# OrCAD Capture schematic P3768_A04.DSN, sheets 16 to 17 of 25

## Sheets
16 0009_PRE-REG 5V: size Custom
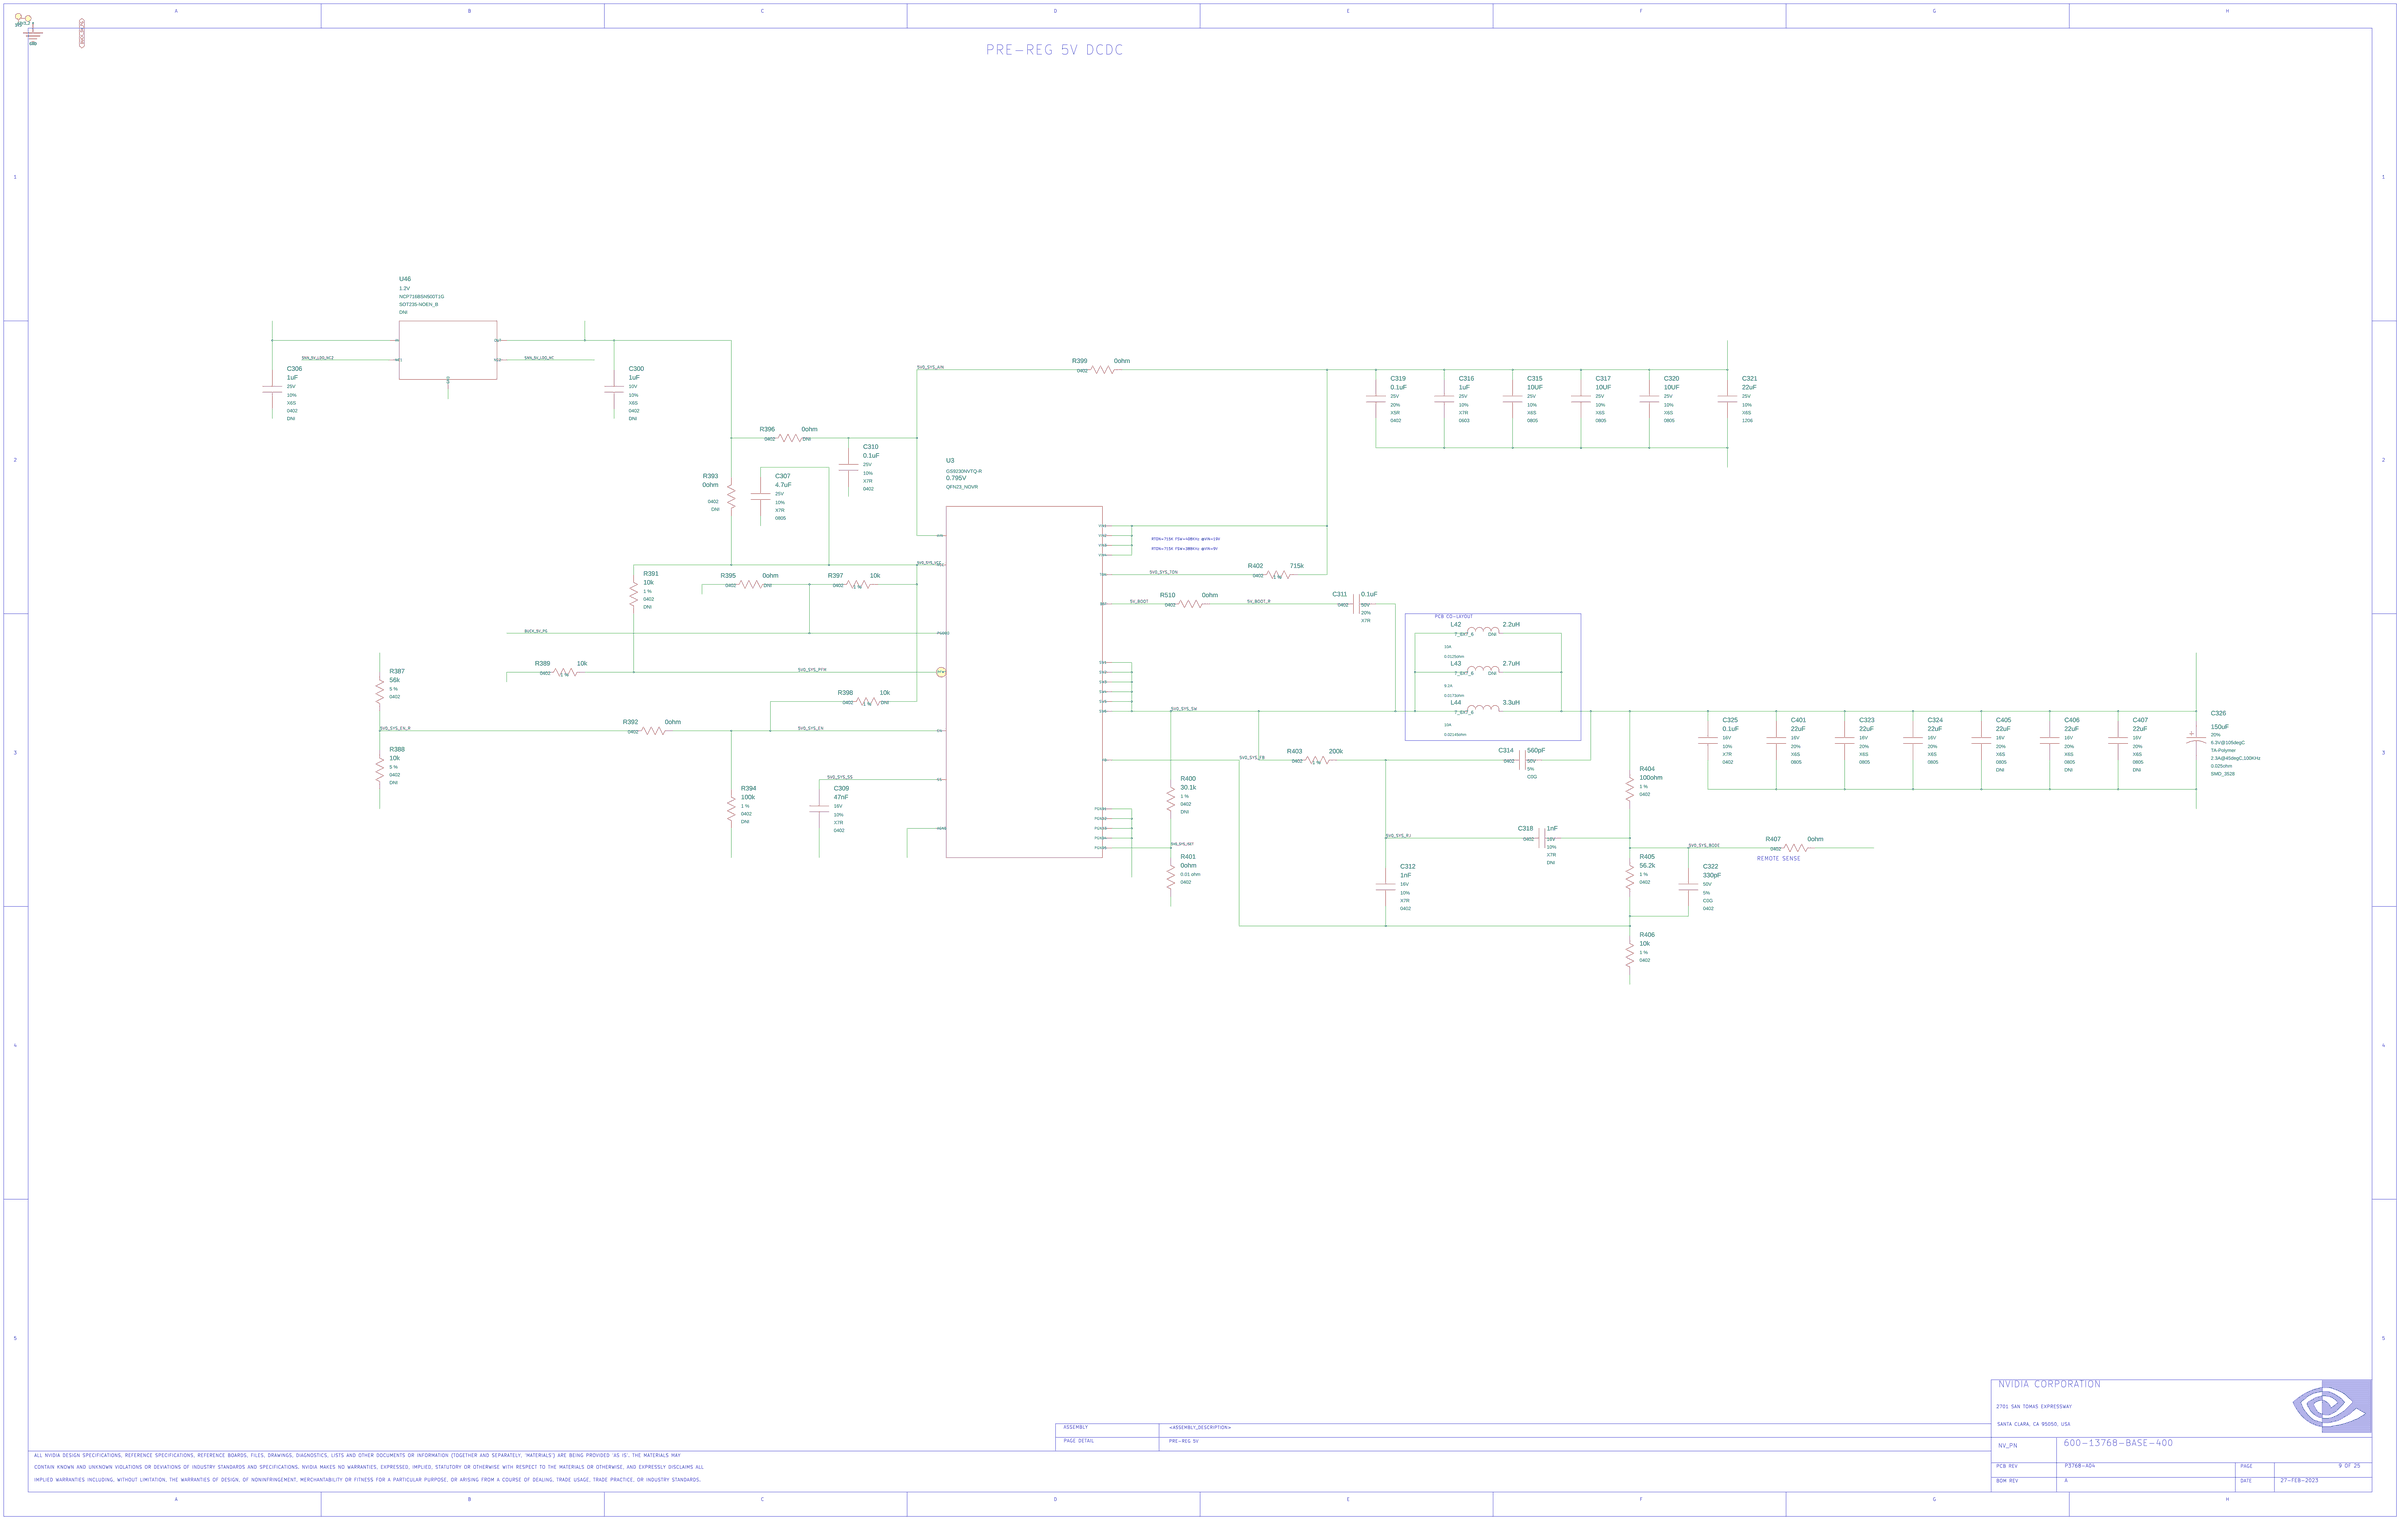
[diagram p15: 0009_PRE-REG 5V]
17 0008_CVM POWER MUX: size Custom
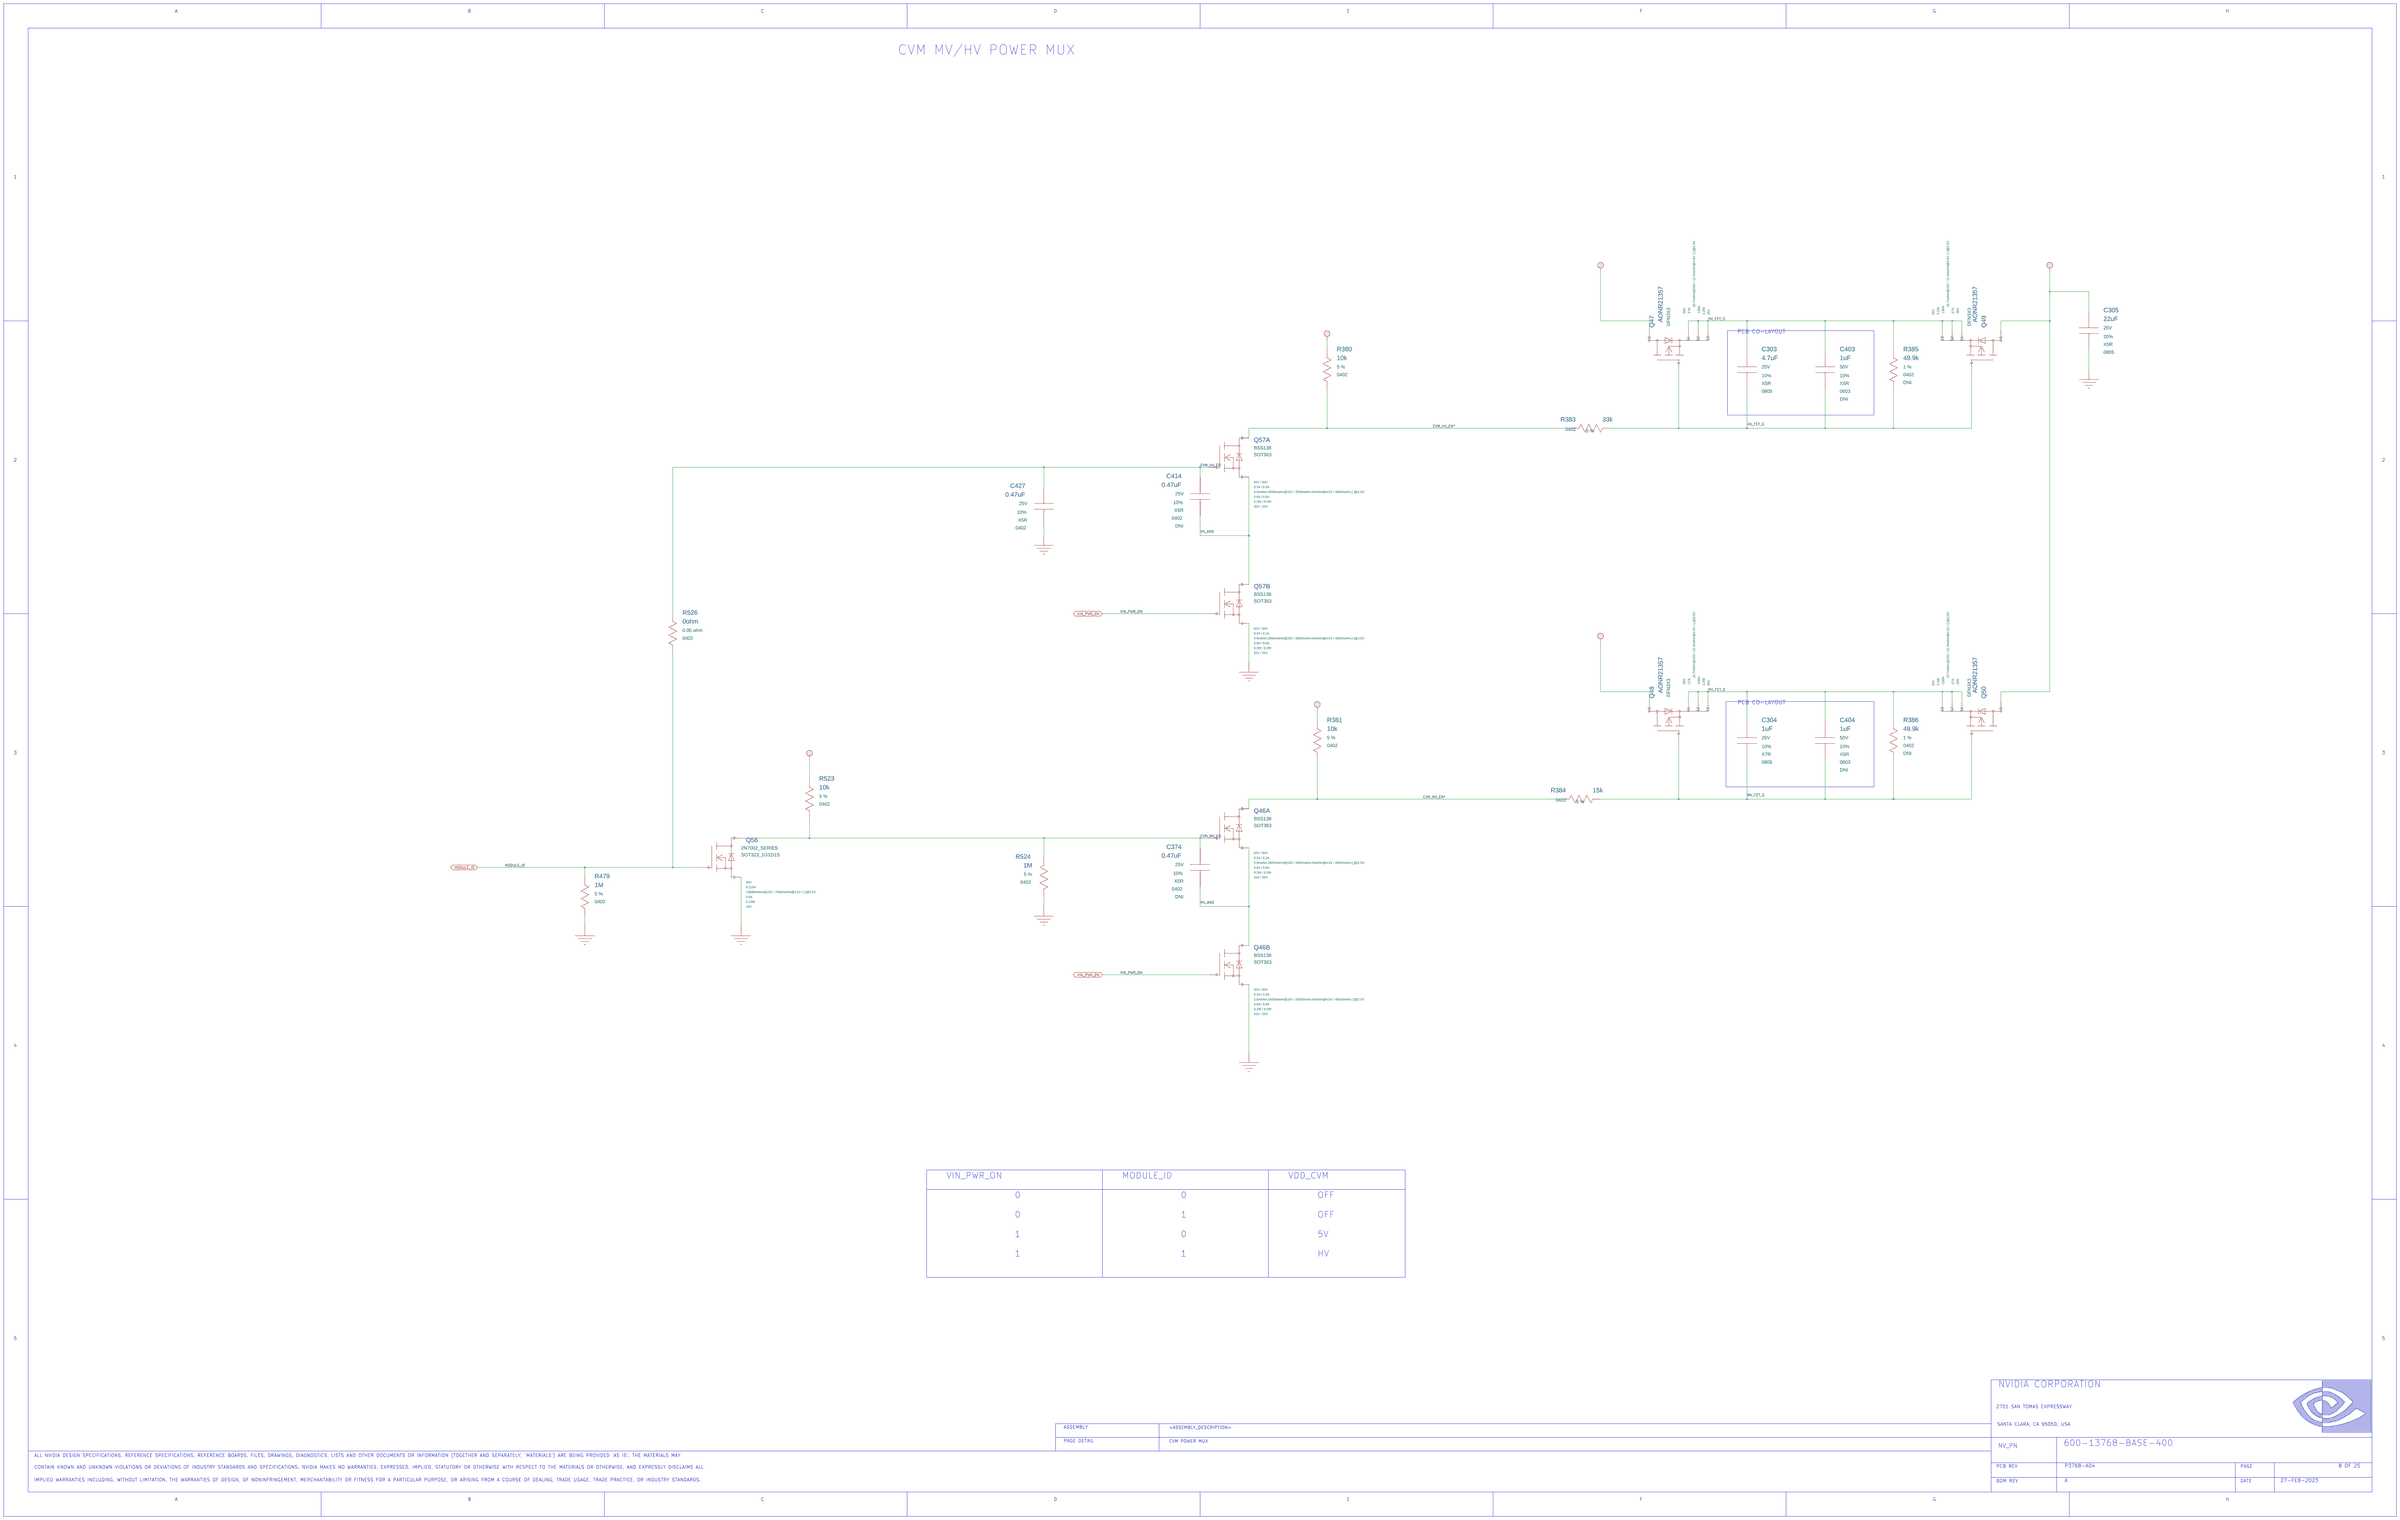
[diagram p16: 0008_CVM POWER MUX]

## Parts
sheet 0008_CVM POWER MUX
C303  4.7uF  [0805U]
C304  1uF  [0805U]
C305  22uF  [0805U]
C374  0.47uF  [0402]
C403  1uF  [0603]
C404  1uF  [0603]
C414  0.47uF  [0402]
C427  0.47uF  [0402]
Q46  Q_FET_N_ENH  [SC70_6]  (sections A,B)
Q47  Q_FET_P_ENH  [DFET_SMD_032X033]
Q48  Q_FET_P_ENH  [DFET_SMD_032X033]
Q49  Q_FET_P_ENH  [DFET_SMD_032X033]
Q50  Q_FET_P_ENH  [DFET_SMD_032X033]
Q56  Q_FET_N_ENH  [SOT323]
Q57  Q_FET_N_ENH  [SC70_6]  (sections A,B)
R380  10k  [0402]
R381  10k  [0402]
R383  33k  [0402]
R384  15k  [0402]
R385  49.9k  [0402]
R386  49.9k  [0402]
R479  1M  [0402]
R523  10k  [0402]
R524  1M  [0402]
R526  0ohm  [0402]
sheet 0009_PRE-REG 5V
C300  1uF  [0402]
C306  1uF  [0402]
C307  4.7uF  [0805U]
C309  47nF  [0402]
C310  0.1uF  [0402]
C311  0.1uF  [0402]
C312  1nF  [0402]
C314  560pF  [0402]
C315  10UF  [0805U]
C316  1uF  [0603]
C317  10UF  [0805U]
C318  1nF  [0402]
C319  0.1uF  [0402]
C320  10UF  [0805U]
C321  22uF  [1206U]
C322  330pF  [0402]
C323  22uF  [0805U]
C324  22uF  [0805U]
C325  0.1uF  [0402]
C326  150uF  [CAP_SMD_3528]
C401  22uF  [0805U]
C405  22uF  [0805U]
C406  22uF  [0805U]
C407  22uF  [0805U]
L42  2.2uH  [IND_NONRKO_SMD_069X069]
L43  2.7uH  [IND_NONRKO_SMD_075X075_B]
L44  3.3uH  [IND_NONRKO_SMD_075X075_B]
R387  56k  [0402]
R388  10k  [0402]
R389  10k  [0402]
R391  10k  [0402]
R392  0ohm  [0402]
R393  0ohm  [0402]
R394  100k  [0402]
R395  0ohm  [0402]
R396  0ohm  [0402]
R397  10k  [0402]
R398  10k  [0402]
R399  0ohm  [0402]
R400  30.1k  [0402]
R401  0ohm  [0402]
R402  715k  [0402]
R403  200k  [0402]
R404  100ohm  [0402]
R405  56.2k  [0402]
R406  10k  [0402]
R407  0ohm  [0402]
R510  0ohm  [0402]
U3  0.795V  [QFN023Q_P050_0040_T028X011_T028X014]
U46  1.2V  [SOT25_5]

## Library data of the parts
C303 = C#1: ASSEMBLY: CVM_POWER_MUX; CDS_LIB: discrete; CDS_PART_NAME: C_0805-4.7UF,X5R,10%,25V,032-2129-000; CDS_PHYS_PART_NAME: C_0805-4.7UF,X5R,10%,25V,032-2129-000-032-2129-000,4.7UF; CDS_SEC: 1; CHIPS_PART_NAME: C; DEVICE_TYPENAME: C_0805-47UFX5R1025V032-2129-000-032-2129-00047UF; DRAWING: @P3768_A04_LIB.P3768_A04(SCH_1):PAGE8; MAT: X5R; MAX_VOLTAGE: 25V; NV_PN: 032-2129-000; PACK_TYPE: 0805; PATH: I95; PHYS_PAGE: 8; ROT: 0; SEC: 1; SIGNAL_MODEL: nv_cap; TOL: 10%; VER: 1; XY: (-3200,5750)
C304 = C#1: ASSEMBLY: CVM_POWER_MUX; CDS_LIB: discrete; CDS_PART_NAME: C_0805-1UF,X7R,10%,25V,036-0117-000; CDS_PHYS_PART_NAME: C_0805-1UF,X7R,10%,25V,036-0117-000-036-0117-000,1UF; CDS_SEC: 1; CHIPS_PART_NAME: C; DEVICE_TYPENAME: C_0805-1UFX7R1025V036-0117-000-036-0117-0001UF; DRAWING: @P3768_A04_LIB.P3768_A04(SCH_1):PAGE8; MAT: X7R; MAX_VOLTAGE: 25V; NV_PN: 036-0117-000; PACK_TYPE: 0805; PATH: I91; PHYS_PAGE: 8; ROT: 0; SEC: 1; SIGNAL_MODEL: nv_cap; TOL: 10%; VER: 1; XY: (-3200,3850)
C305 = C#1: ASSEMBLY: CVM_POWER_MUX; CDS_LIB: discrete; CDS_PART_NAME: C_0805-22UF,X5R,20%,25V,032-1308-000; CDS_PHYS_PART_NAME: C_0805-22UF,X5R,20%,25V,032-1308-000-032-1308-000,22UF; CDS_SEC: 1; CHIPS_PART_NAME: C; DEVICE_TYPENAME: C_0805-22UFX5R2025V032-1308-000-032-1308-00022UF; DRAWING: @P3768_A04_LIB.P3768_A04(SCH_1):PAGE8; MAT: X5R; MAX_VOLTAGE: 25V; NV_PN: 032-1308-000; PACK_TYPE: 0805; PATH: I78; PHYS_PAGE: 8; ROT: 0; SEC: 1; SIGNAL_MODEL: nv_cap; TOL: 20%; VER: 1; XY: (-1450,5950)
C374 = C#1: ASSEMBLY: CVM_POWER_MUX; CDS_LIB: discrete; CDS_PART_NAME: C_0402-0.47UF,X5R,10%,25V,032-0306-000; CDS_PHYS_PART_NAME: C_0402-0.47UF,X5R,10%,25V,032-0306-000-0.47UF,032-0306-000; CDS_SEC: 1; CHIPS_PART_NAME: C; DEVICE_TYPENAME: C_0402-047UFX5R1025V032-0306-000-047UF032-0306-000; DRAWING: @P3768_A04_LIB.P3768_A04(SCH_1):PAGE8; MAT: X5R; MAX_VOLTAGE: 25V; NV_PN: 032-0306-000; PATH: I82; PHYS_PAGE: 8; ROT: 2; SEC: 1; SIGNAL_MODEL: nv_cap; SKU: DNI; TOL: 10%; VER: 1; XY: (-6000,3200)
C403 = C#1: ASSEMBLY: CVM_POWER_MUX; CDS_LIB: discrete; CDS_PART_NAME: C_0603-1UF,X5R,10%,50V,039-0222-000; CDS_PHYS_PART_NAME: C_0603-1UF,X5R,10%,50V,039-0222-000-039-0222-000,1UF; CDS_SEC: 1; CHIPS_PART_NAME: C; DEVICE_TYPENAME: C_0603-1UFX5R1050V039-0222-000-039-0222-0001UF; DRAWING: @P3768_A04_LIB.P3768_A04(SCH_1):PAGE8; MAT: X5R; MAX_VOLTAGE: 50V; NV_PN: 039-0222-000; PATH: I92; PHYS_PAGE: 8; ROT: 0; SEC: 1; SIGNAL_MODEL: nv_cap; SKU: DNI; TOL: 10%; VER: 1; XY: (-2800,5750)
C404 = C#1: ASSEMBLY: CVM_POWER_MUX; CDS_LIB: discrete; CDS_PART_NAME: C_0603-1UF,X5R,10%,50V,039-0222-000; CDS_PHYS_PART_NAME: C_0603-1UF,X5R,10%,50V,039-0222-000-039-0222-000,1UF; CDS_SEC: 1; CHIPS_PART_NAME: C; DEVICE_TYPENAME: C_0603-1UFX5R1050V039-0222-000-039-0222-0001UF; DRAWING: @P3768_A04_LIB.P3768_A04(SCH_1):PAGE8; MAT: X5R; MAX_VOLTAGE: 50V; NV_PN: 039-0222-000; PATH: I93; PHYS_PAGE: 8; ROT: 0; SEC: 1; SIGNAL_MODEL: nv_cap; SKU: DNI; TOL: 10%; VER: 1; XY: (-2800,3850)
C414 = C#1: ASSEMBLY: CVM_POWER_MUX; CDS_LIB: discrete; CDS_PART_NAME: C_0402-0.47UF,X5R,10%,25V,032-0306-000; CDS_PHYS_PART_NAME: C_0402-0.47UF,X5R,10%,25V,032-0306-000-0.47UF,032-0306-000; CDS_SEC: 1; CHIPS_PART_NAME: C; DEVICE_TYPENAME: C_0402-047UFX5R1025V032-0306-000-047UF032-0306-000; DRAWING: @P3768_A04_LIB.P3768_A04(SCH_1):PAGE8; MAT: X5R; MAX_VOLTAGE: 25V; NV_PN: 032-0306-000; PATH: I177; PHYS_PAGE: 8; ROT: 2; SEC: 1; SIGNAL_MODEL: nv_cap; SKU: DNI; TOL: 10%; VER: 1; XY: (-6000,5100)
C427 = C#1: ASSEMBLY: CVM_POWER_MUX; CDS_LIB: discrete; CDS_PART_NAME: C_0402-0.47UF,X5R,10%,25V,032-0306-000; CDS_PHYS_PART_NAME: C_0402-0.47UF,X5R,10%,25V,032-0306-000-0.47UF,032-0306-000; CDS_SEC: 1; CHIPS_PART_NAME: C; DEVICE_TYPENAME: C_0402-047UFX5R1025V032-0306-000-047UF032-0306-000; DRAWING: @P3768_A04_LIB.P3768_A04(SCH_1):PAGE8; MAT: X5R; MAX_VOLTAGE: 25V; NV_PN: 032-0306-000; PATH: I178; PHYS_PAGE: 8; ROT: 2; SEC: 1; SIGNAL_MODEL: nv_cap; TOL: 10%; VER: 1; XY: (-6800,5050)
Q46 = Q_FET_N_ENH: ASSEMBLY: CVM_POWER_MUX; CDS_LIB: discrete; CDS_PART_NAME: Q_FET_N_ENH_SOT363-BSS138,50V / 50V,3.5MOHM,3500MOHM@10V / 2500MOHM,0MOHM@4.5V / 4500MOHM,[ ]@2.5V,0.2A / 0.2A,0.6A / 0.6A,20V / 20V,0.2W / 0.2W,[ ],[ ]@10V / 1NC,1NC@4.5V / [ ],[ ]@2.5V,300-1278-000; CDS_PHYS_PART_NAME: Q_FET_N_ENH_SOT363-BSS138,50V / 50V,3.5MOHM,3500MOHM@10V / 2500MOHM,0MOHM@4.5V / 4500MOHM,[ ]@2.5V,0.2A / 0.2A,0.6A / 0.6A,20VB; CDS_SEC: 2; CONTINUOUS_CURRENT: 0.2A / 0.2A; DEVICE_TYPENAME: Q_FET_N_ENH_SOT363-BSS13850V50V35MOHM3500MOHM10V2500MOHM0MOHM45V4500MOHM25V02A02A06A06A20VB; DRAWING: @P3768_A04_LIB.P3768_A04(SCH_1):PAGE8; MAX_CURRENT: 0.6A / 0.6A; MAX_VOLTAGE: 50V / 50V; MAX_WATTAGE: 0.2W / 0.2W; NV_NAME: BSS138; NV_PN: 300-1278-000; PACK_TYPE: SOT363; PATH: I170; PHYS_PAGE: 8; Q_G: [ ],[ ]@10V / 1nC,1nC@4.5V / [ ],[ ]@2.5V; ROT: 0; R_DS_ON: 3.5mohm,3500mohm@10V / 2500mohm,0mohm@4.5V / 4500mohm,[ ]@2.5V; SEC: 2; SEC_TYPE: SOT363; VER: 2; V_BE_GS: 20V / 20V; XY: (-5850,2700)
Q47 = Q_FET_P_ENH: ASSEMBLY: CVM_POWER_MUX; CDS_LIB: discrete; CDS_PART_NAME: Q_FET_P_ENH_DFN3X3-AONR21357,-30V,10.7MOHM@10V / 12.3MOHM@4.5V / [ ]@2.5V,-17A,-136A,25V,3.2W,70NC@10V / 35NC@4.5V / [ ]@2.5V,300-1070-000; CDS_PHYS_PART_NAME: Q_FET_P_ENH_DFN3X3-AONR21357,-30V,10.7MOHM@10V / 12.3MOHM@4.5V / [ ]@2.5V,-17A,-136A,25V,3.2W,70NC@10V / 35NC@4.5V / [ ]@2.5V,B; CDS_SEC: 1; CONTINUOUS_CURRENT: -17A; DEVICE_TYPENAME: Q_FET_P_ENH_DFN3X3-AONR21357-30V107MOHM10V123MOHM45V25V-17A-136A25V32W70NC10V35NC45V25VB; DRAWING: @P3768_A04_LIB.P3768_A04(SCH_1):PAGE8; MAX_CURRENT: -136A; MAX_VOLTAGE: -30V; MAX_WATTAGE: 3.2W; NV_NAME: AONR21357; NV_PN: 300-1070-000; PACK_TYPE: DFN3X3; PATH: I72; PHYS_PAGE: 8; Q_G: 70nC@10V / 35nC@4.5V / [ ]@2.5V; ROT: 1; R_DS_ON: 10.7mohm@10V / 12.3mohm@4.5V / [ ]@2.5V; SEC: 1; VER: 8; V_BE_GS: 25V; XY: (-3600,5850)
Q48 = Q_FET_P_ENH: ASSEMBLY: CVM_POWER_MUX; CDS_LIB: discrete; CDS_PART_NAME: Q_FET_P_ENH_DFN3X3-AONR21357,-30V,10.7MOHM@10V / 12.3MOHM@4.5V / [ ]@2.5V,-17A,-136A,25V,3.2W,70NC@10V / 35NC@4.5V / [ ]@2.5V,300-1070-000; CDS_PHYS_PART_NAME: Q_FET_P_ENH_DFN3X3-AONR21357,-30V,10.7MOHM@10V / 12.3MOHM@4.5V / [ ]@2.5V,-17A,-136A,25V,3.2W,70NC@10V / 35NC@4.5V / [ ]@2.5V,B; CDS_SEC: 1; CONTINUOUS_CURRENT: -17A; DEVICE_TYPENAME: Q_FET_P_ENH_DFN3X3-AONR21357-30V107MOHM10V123MOHM45V25V-17A-136A25V32W70NC10V35NC45V25VB; DRAWING: @P3768_A04_LIB.P3768_A04(SCH_1):PAGE8; MAX_CURRENT: -136A; MAX_VOLTAGE: -30V; MAX_WATTAGE: 3.2W; NV_NAME: AONR21357; NV_PN: 300-1070-000; PACK_TYPE: DFN3X3; PATH: I69; PHYS_PAGE: 8; Q_G: 70nC@10V / 35nC@4.5V / [ ]@2.5V; ROT: 1; R_DS_ON: 10.7mohm@10V / 12.3mohm@4.5V / [ ]@2.5V; SEC: 1; VER: 8; V_BE_GS: 25V; XY: (-3600,3950)
Q49 = Q_FET_P_ENH: ASSEMBLY: CVM_POWER_MUX; CDS_LIB: discrete; CDS_PART_NAME: Q_FET_P_ENH_DFN3X3-AONR21357,-30V,10.7MOHM@10V / 12.3MOHM@4.5V / [ ]@2.5V,-17A,-136A,25V,3.2W,70NC@10V / 35NC@4.5V / [ ]@2.5V,300-1070-000; CDS_PHYS_PART_NAME: Q_FET_P_ENH_DFN3X3-AONR21357,-30V,10.7MOHM@10V / 12.3MOHM@4.5V / [ ]@2.5V,-17A,-136A,25V,3.2W,70NC@10V / 35NC@4.5V / [ ]@2.5V,B; CDS_SEC: 1; CONTINUOUS_CURRENT: -17A; DEVICE_TYPENAME: Q_FET_P_ENH_DFN3X3-AONR21357-30V107MOHM10V123MOHM45V25V-17A-136A25V32W70NC10V35NC45V25VB; DRAWING: @P3768_A04_LIB.P3768_A04(SCH_1):PAGE8; MAX_CURRENT: -136A; MAX_VOLTAGE: -30V; MAX_WATTAGE: 3.2W; NV_NAME: AONR21357; NV_PN: 300-1070-000; PACK_TYPE: DFN3X3; PATH: I76; PHYS_PAGE: 8; Q_G: 70nC@10V / 35nC@4.5V / [ ]@2.5V; ROT: 7; R_DS_ON: 10.7mohm@10V / 12.3mohm@4.5V / [ ]@2.5V; SEC: 1; VER: 8; V_BE_GS: 25V; XY: (-2000,5850)
Q50 = Q_FET_P_ENH: ASSEMBLY: CVM_POWER_MUX; CDS_LIB: discrete; CDS_PART_NAME: Q_FET_P_ENH_DFN3X3-AONR21357,-30V,10.7MOHM@10V / 12.3MOHM@4.5V / [ ]@2.5V,-17A,-136A,25V,3.2W,70NC@10V / 35NC@4.5V / [ ]@2.5V,300-1070-000; CDS_PHYS_PART_NAME: Q_FET_P_ENH_DFN3X3-AONR21357,-30V,10.7MOHM@10V / 12.3MOHM@4.5V / [ ]@2.5V,-17A,-136A,25V,3.2W,70NC@10V / 35NC@4.5V / [ ]@2.5V,B; CDS_SEC: 1; CONTINUOUS_CURRENT: -17A; DEVICE_TYPENAME: Q_FET_P_ENH_DFN3X3-AONR21357-30V107MOHM10V123MOHM45V25V-17A-136A25V32W70NC10V35NC45V25VB; DRAWING: @P3768_A04_LIB.P3768_A04(SCH_1):PAGE8; MAX_CURRENT: -136A; MAX_VOLTAGE: -30V; MAX_WATTAGE: 3.2W; NV_NAME: AONR21357; NV_PN: 300-1070-000; PACK_TYPE: DFN3X3; PATH: I75; PHYS_PAGE: 8; Q_G: 70nC@10V / 35nC@4.5V / [ ]@2.5V; ROT: 7; R_DS_ON: 10.7mohm@10V / 12.3mohm@4.5V / [ ]@2.5V; SEC: 1; VER: 8; V_BE_GS: 25V; XY: (-2000,3950)
Q56 = Q_FET_N_ENH#1: ASSEMBLY: CVM_POWER_MUX; CDS_LIB: discrete; CDS_PART_NAME: Q_FET_N_ENH_SOT323_1G1D1S-2N7002_SERIES,60V,13500MOHM@10V / 7500MOHM@4.5V / [ ]@2.5V,0.115A,0.8A,20V,0.15W,[ ]@10V / 0.5NC@4.5V / [ ]@2.5V,300-1133-000; CDS_PHYS_PART_NAME: Q_FET_N_ENH_SOT323_1G1D1S-2N7002_SERIES,60V,13500MOHM@10V / 7500MOHM@4.5V / [ ]@2.5V,0.115A,0.8A,20V,0.15W,[ ]@10V / 0.5NC@4.5B; CDS_SEC: 1; CONTINUOUS_CURRENT: 0.115A; CaptureCellPackProp: Q_FET_N_ENH##1; DEVICE_TYPENAME: Q_FET_N_ENH_SOT323_1G1D1S-2N7002_SERIES60V13500MOHM10V7500MOHM45V25V0115A08A20V015W10V05NC45B; DRAWING: @P3768_A04_LIB.P3768_A04(SCH_1):PAGE8; MAX_CURRENT: 0.8A; MAX_VOLTAGE: 60V; MAX_WATTAGE: 0.15W; NV_NAME: 2N7002_SERIES; NV_PN: 300-1133-000; PACK_TYPE: SOT323_1G1D1S; PATH: I166; PHYS_PAGE: 8; Q_G: [ ]@10V / 0.5nC@4.5V / [ ]@2.5V; ROT: 0; R_DS_ON: 13500mohm@10V / 7500mohm@4.5V / [ ]@2.5V; SEC: 1; VER: 2; V_BE_GS: 20V; XY: (-8450,3250)
Q57 = Q_FET_N_ENH: ASSEMBLY: CVM_POWER_MUX; CDS_LIB: discrete; CDS_PART_NAME: Q_FET_N_ENH_SOT363-BSS138,50V / 50V,3.5MOHM,3500MOHM@10V / 2500MOHM,0MOHM@4.5V / 4500MOHM,[ ]@2.5V,0.2A / 0.2A,0.6A / 0.6A,20V / 20V,0.2W / 0.2W,[ ],[ ]@10V / 1NC,1NC@4.5V / [ ],[ ]@2.5V,300-1278-000; CDS_PHYS_PART_NAME: Q_FET_N_ENH_SOT363-BSS138,50V / 50V,3.5MOHM,3500MOHM@10V / 2500MOHM,0MOHM@4.5V / 4500MOHM,[ ]@2.5V,0.2A / 0.2A,0.6A / 0.6A,20VB; CDS_SEC: 1; CONTINUOUS_CURRENT: 0.2A / 0.2A; DEVICE_TYPENAME: Q_FET_N_ENH_SOT363-BSS13850V50V35MOHM3500MOHM10V2500MOHM0MOHM45V4500MOHM25V02A02A06A06A20VB; DRAWING: @P3768_A04_LIB.P3768_A04(SCH_1):PAGE8; MAX_CURRENT: 0.6A / 0.6A; MAX_VOLTAGE: 50V / 50V; MAX_WATTAGE: 0.2W / 0.2W; NV_NAME: BSS138; NV_PN: 300-1278-000; PACK_TYPE: SOT363; PATH: I169; PHYS_PAGE: 8; Q_G: [ ],[ ]@10V / 1nC,1nC@4.5V / [ ],[ ]@2.5V; ROT: 0; R_DS_ON: 3.5mohm,3500mohm@10V / 2500mohm,0mohm@4.5V / 4500mohm,[ ]@2.5V; SEC: 1; SEC_TYPE: SOT363; VER: 2; V_BE_GS: 20V / 20V; XY: (-5850,5300)
R380 = R: ASSEMBLY: CVM_POWER_MUX; CDS_LIB: discrete; CDS_PART_NAME: R_0402-10K,5 %,62.5MW,195-0486-000; CDS_PHYS_PART_NAME: R_0402-10K,5 %,62.5MW,195-0486-000-10K,195-0486-000; CDS_SEC: 1; DEVICE_TYPENAME: R_0402-10K5625MW195-0486-000-10K195-0486-000; DRAWING: @P3768_A04_LIB.P3768_A04(SCH_1):PAGE8; MAX_WATTAGE: 62.5mW; NV_PN: 195-0486-000; PATH: I80; PHYS_PAGE: 8; ROT: 0; SEC: 1; SIGNAL_MODEL: nv_res; TOL: 5 %; VER: 2; XY: (-5350,5750)
R381 = R: ASSEMBLY: CVM_POWER_MUX; CDS_LIB: discrete; CDS_PART_NAME: R_0402-10K,5 %,62.5MW,195-0486-000; CDS_PHYS_PART_NAME: R_0402-10K,5 %,62.5MW,195-0486-000-10K,195-0486-000; CDS_SEC: 1; DEVICE_TYPENAME: R_0402-10K5625MW195-0486-000-10K195-0486-000; DRAWING: @P3768_A04_LIB.P3768_A04(SCH_1):PAGE8; MAX_WATTAGE: 62.5mW; NV_PN: 195-0486-000; PATH: I81; PHYS_PAGE: 8; ROT: 0; SEC: 1; SIGNAL_MODEL: nv_res; TOL: 5 %; VER: 2; XY: (-5400,3850)
R383 = R#1: ASSEMBLY: CVM_POWER_MUX; CDS_LIB: discrete; CDS_PART_NAME: R_0402-33K,5 %,62.5MW,195-0571-000; CDS_PHYS_PART_NAME: R_0402-33K,5 %,62.5MW,195-0571-000-195-0571-000,33K; CDS_SEC: 1; CHIPS_PART_NAME: R; DEVICE_TYPENAME: R_0402-33K5625MW195-0571-000-195-0571-00033K; DRAWING: @P3768_A04_LIB.P3768_A04(SCH_1):PAGE8; MAX_WATTAGE: 62.5mW; NV_PN: 195-0571-000; PATH: I94; PHYS_PAGE: 8; ROT: 0; SEC: 1; SIGNAL_MODEL: nv_res; TOL: 5 %; VER: 1; XY: (-4000,5450)
R384 = R#1: ASSEMBLY: CVM_POWER_MUX; CDS_LIB: discrete; CDS_PART_NAME: R_0402-15K,5 %,62.5MW,195-0515-000; CDS_PHYS_PART_NAME: R_0402-15K,5 %,62.5MW,195-0515-000-15K,195-0515-000; CDS_SEC: 1; CHIPS_PART_NAME: R; DEVICE_TYPENAME: R_0402-15K5625MW195-0515-000-15K195-0515-000; DRAWING: @P3768_A04_LIB.P3768_A04(SCH_1):PAGE8; MAX_WATTAGE: 62.5mW; NV_PN: 195-0515-000; PATH: I136; PHYS_PAGE: 8; ROT: 0; SEC: 1; SIGNAL_MODEL: nv_res; TOL: 5 %; VER: 1; XY: (-4050,3550)
R385 = R: ASSEMBLY: CVM_POWER_MUX; CDS_LIB: discrete; CDS_PART_NAME: R_0402-49.9K,1 %,62.5MW,195-0340-000; CDS_PHYS_PART_NAME: R_0402-49.9K,1 %,62.5MW,195-0340-000-195-0340-000,49.9K; CDS_SEC: 1; DEVICE_TYPENAME: R_0402-499K1625MW195-0340-000-195-0340-000499K; DRAWING: @P3768_A04_LIB.P3768_A04(SCH_1):PAGE8; MAX_WATTAGE: 62.5mW; NV_PN: 195-0340-000; PATH: I87; PHYS_PAGE: 8; ROT: 0; SEC: 1; SIGNAL_MODEL: nv_res; SKU: DNI; TOL: 1 %; VER: 2; XY: (-2450,5750)
R386 = R: ASSEMBLY: CVM_POWER_MUX; CDS_LIB: discrete; CDS_PART_NAME: R_0402-49.9K,1 %,62.5MW,195-0340-000; CDS_PHYS_PART_NAME: R_0402-49.9K,1 %,62.5MW,195-0340-000-195-0340-000,49.9K; CDS_SEC: 1; DEVICE_TYPENAME: R_0402-499K1625MW195-0340-000-195-0340-000499K; DRAWING: @P3768_A04_LIB.P3768_A04(SCH_1):PAGE8; MAX_WATTAGE: 62.5mW; NV_PN: 195-0340-000; PATH: I89; PHYS_PAGE: 8; ROT: 0; SEC: 1; SIGNAL_MODEL: nv_res; SKU: DNI; TOL: 1 %; VER: 2; XY: (-2450,3850)
R479 = R: ASSEMBLY: CVM_POWER_MUX; CDS_LIB: discrete; CDS_PART_NAME: R_0402-1M,5 %,62.5MW,195-0488-000; CDS_PHYS_PART_NAME: R_0402-1M,5 %,62.5MW,195-0488-000-195-0488-000,1M; CDS_SEC: 1; DEVICE_TYPENAME: R_0402-1M5625MW195-0488-000-195-0488-0001M; DRAWING: @P3768_A04_LIB.P3768_A04(SCH_1):PAGE8; MAX_WATTAGE: 62.5mW; NV_PN: 195-0488-000; PATH: I151; PHYS_PAGE: 8; ROT: 0; SEC: 1; SIGNAL_MODEL: nv_res; TOL: 5 %; VER: 2; XY: (-9150,3050)
R523 = R: ASSEMBLY: CVM_POWER_MUX; CDS_LIB: discrete; CDS_PART_NAME: R_0402-10K,5 %,62.5MW,195-0486-000; CDS_PHYS_PART_NAME: R_0402-10K,5 %,62.5MW,195-0486-000-10K,195-0486-000; CDS_SEC: 1; DEVICE_TYPENAME: R_0402-10K5625MW195-0486-000-10K195-0486-000; DRAWING: @P3768_A04_LIB.P3768_A04(SCH_1):PAGE8; MAX_WATTAGE: 62.5mW; NV_PN: 195-0486-000; PATH: I114; PHYS_PAGE: 8; ROT: 0; SEC: 1; SIGNAL_MODEL: nv_res; TOL: 5 %; VER: 2; XY: (-8000,3550)
R524 = R: ASSEMBLY: CVM_POWER_MUX; CDS_LIB: discrete; CDS_PART_NAME: R_0402-1M,5 %,62.5MW,195-0488-000; CDS_PHYS_PART_NAME: R_0402-1M,5 %,62.5MW,195-0488-000-195-0488-000,1M; CDS_SEC: 1; DEVICE_TYPENAME: R_0402-1M5625MW195-0488-000-195-0488-0001M; DRAWING: @P3768_A04_LIB.P3768_A04(SCH_1):PAGE8; MAX_WATTAGE: 62.5mW; NV_PN: 195-0488-000; PATH: I99; PHYS_PAGE: 8; ROT: 2; SEC: 1; SIGNAL_MODEL: nv_res; TOL: 5 %; VER: 2; XY: (-6800,3150)
R526 = R: ASSEMBLY: CVM_POWER_MUX; CDS_LIB: discrete; CDS_PART_NAME: R_0402-0OHM,0.05 OHM,62.5MW,195-2655-000; CDS_PHYS_PART_NAME: R_0402-0OHM,0.05 OHM,62.5MW,195-2655-000-0OHM,195-2655-000; CDS_SEC: 1; DEVICE_TYPENAME: R_0402-0OHM005OHM625MW195-2655-000-0OHM195-2655-000; DRAWING: @P3768_A04_LIB.P3768_A04(SCH_1):PAGE8; MAX_WATTAGE: 62.5mW; NV_PN: 195-2655-000; PATH: I165; PHYS_PAGE: 8; ROT: 0; SEC: 1; SIGNAL_MODEL: nv_res; TOL: 0.05 ohm; VER: 2; XY: (-8700,4400)
C300 = C#1: ASSEMBLY: PS_5V; CDS_LIB: discrete; CDS_PART_NAME: C_0402-1UF,X6S,10%,10V,032-0776-000; CDS_PHYS_PART_NAME: C_0402-1UF,X6S,10%,10V,032-0776-000-032-0776-000,1UF; CDS_SEC: 1; CHIPS_PART_NAME: C; DEVICE_TYPENAME: C_0402-1UFX6S1010V032-0776-000-032-0776-0001UF; DRAWING: @P3768_A04_LIB.P3768_A04(SCH_1):PAGE9; MAT: X6S; MAX_VOLTAGE: 10V; NV_PN: 032-0776-000; PATH: I129; PHYS_PAGE: 9; PSPICETEMPLATE: X^@REFDES  %1    %2   @NV_PN; ROT: 0; SEC: 1; SIGNAL_MODEL: nv_cap; SKU: DNI; TOL: 10%; VER: 1; XY: (-9000,5650)
C306 = C#1: ASSEMBLY: PS_5V; CDS_LIB: discrete; CDS_PART_NAME: C_0402-1UF,X6S,10%,25V,032-0782-000; CDS_PHYS_PART_NAME: C_0402-1UF,X6S,10%,25V,032-0782-000-032-0782-000,1UF; CDS_SEC: 1; CHIPS_PART_NAME: C; DEVICE_TYPENAME: C_0402-1UFX6S1025V032-0782-000-032-0782-0001UF; DRAWING: @P3768_A04_LIB.P3768_A04(SCH_1):PAGE9; MAT: X6S; MAX_VOLTAGE: 25V; NV_PN: 032-0782-000; PATH: I128; PHYS_PAGE: 9; PSPICETEMPLATE: X^@REFDES  %1    %2   @NV_PN; ROT: 0; SEC: 1; SIGNAL_MODEL: nv_cap; SKU: DNI; TOL: 10%; VER: 1; XY: (-10750,5650)
C307 = C#1: ASSEMBLY: PS_5V; CDS_LIB: discrete; CDS_PART_NAME: C_0805-4.7UF,X7R,10%,25V,032-0207-000; CDS_PHYS_PART_NAME: C_0805-4.7UF,X7R,10%,25V,032-0207-000-032-0207-000,4.7UF; CDS_SEC: 1; CHIPS_PART_NAME: C; DEVICE_TYPENAME: C_0805-47UFX7R1025V032-0207-000-032-0207-00047UF; DRAWING: @P3768_A04_LIB.P3768_A04(SCH_1):PAGE9; MAT: X7R; MAX_VOLTAGE: 25V; NV_PN: 032-0207-000; PACK_TYPE: 0805; PATH: I134; PHYS_PAGE: 9; PSPICETEMPLATE: X^@REFDES  %1    %2   @NV_PN; ROT: 0; SEC: 1; SIGNAL_MODEL: nv_cap; TOL: 10%; VER: 1; XY: (-8250,5100)
C309 = C#1: ASSEMBLY: PS_5V; CDS_LIB: discrete; CDS_PART_NAME: C_0402-47NF,X7R,10%,16V,036-0018-000; CDS_PHYS_PART_NAME: C_0402-47NF,X7R,10%,16V,036-0018-000-036-0018-000,47NF; CDS_SEC: 1; CHIPS_PART_NAME: C; DEVICE_TYPENAME: C_0402-47NFX7R1016V036-0018-000-036-0018-00047NF; DRAWING: @P3768_A04_LIB.P3768_A04(SCH_1):PAGE9; MAT: X7R; MAX_VOLTAGE: 16V; NV_PN: 036-0018-000; PATH: I165; PHYS_PAGE: 9; PSPICETEMPLATE: X^@REFDES  %1    %2   @NV_PN; ROT: 0; SEC: 1; SIGNAL_MODEL: nv_cap; TOL: 10%; VER: 1; XY: (-7950,3500)
C310 = C#1: ASSEMBLY: PS_5V; CDS_LIB: discrete; CDS_PART_NAME: C_0402-0.1UF,X7R,10%,25V,032-1700-000; CDS_PHYS_PART_NAME: C_0402-0.1UF,X7R,10%,25V,032-1700-000-0.1UF,032-1700-000; CDS_SEC: 1; CHIPS_PART_NAME: C; DEVICE_TYPENAME: C_0402-01UFX7R1025V032-1700-000-01UF032-1700-000; DRAWING: @P3768_A04_LIB.P3768_A04(SCH_1):PAGE9; MAT: X7R; MAX_VOLTAGE: 25V; NV_PN: 032-1700-000; PATH: I135; PHYS_PAGE: 9; PSPICETEMPLATE: X^@REFDES  %1    %2   @NV_PN; ROT: 0; SEC: 1; SIGNAL_MODEL: nv_cap; TOL: 10%; VER: 1; XY: (-7800,5250)
C311 = C: ASSEMBLY: PS_5V; CDS_LIB: discrete; CDS_PART_NAME: C_0402-0.1UF,X7R,20%,50V,032-0892-000; CDS_PHYS_PART_NAME: C_0402-0.1UF,X7R,20%,50V,032-0892-000-0.1UF,032-0892-000; CDS_SEC: 1; DEVICE_TYPENAME: C_0402-01UFX7R2050V032-0892-000-01UF032-0892-000; DRAWING: @P3768_A04_LIB.P3768_A04(SCH_1):PAGE9; MAT: X7R; MAX_VOLTAGE: 50V; NV_PN: 032-0892-000; PATH: I145; PHYS_PAGE: 9; PSPICETEMPLATE: X^@REFDES  %1    %2   @NV_PN; ROT: 0; SEC: 1; SIGNAL_MODEL: nv_cap; TOL: 20%; VER: 2; XY: (-5200,4550)
C312 = C#1: ASSEMBLY: PS_5V; CDS_LIB: discrete; CDS_PART_NAME: C_0402-1NF,X7R,10%,16V,036-0012-000; CDS_PHYS_PART_NAME: C_0402-1NF,X7R,10%,16V,036-0012-000-036-0012-000,1NF; CDS_SEC: 1; CHIPS_PART_NAME: C; DEVICE_TYPENAME: C_0402-1NFX7R1016V036-0012-000-036-0012-0001NF; DRAWING: @P3768_A04_LIB.P3768_A04(SCH_1):PAGE9; MAT: X7R; MAX_VOLTAGE: 16V; NV_PN: 036-0012-000; PATH: I160; PHYS_PAGE: 9; PSPICETEMPLATE: X^@REFDES  %1    %2   @NV_PN; ROT: 0; SEC: 1; SIGNAL_MODEL: nv_cap; TOL: 10%; VER: 1; XY: (-5050,3100)
C314 = C: ASSEMBLY: PS_5V; CDS_LIB: discrete; CDS_PART_NAME: C_0402-560PF,C0G,5%,50V,035-0295-000; CDS_PHYS_PART_NAME: C_0402-560PF,C0G,5%,50V,035-0295-000-035-0295-000,560PF; CDS_SEC: 1; DEVICE_TYPENAME: C_0402-560PFC0G550V035-0295-000-035-0295-000560PF; DRAWING: @P3768_A04_LIB.P3768_A04(SCH_1):PAGE9; MAT: C0G; MAX_VOLTAGE: 50V; NV_PN: 035-0295-000; PATH: I196; PHYS_PAGE: 9; ROT: 0; SEC: 1; SIGNAL_MODEL: nv_cap; TOL: 5%; VER: 2; XY: (-4350,3750)
C315 = C#1: ASSEMBLY: PS_5V; CDS_LIB: discrete; CDS_PART_NAME: C_0805-10UF,X6S,10%,25V,032-0728-000; CDS_PHYS_PART_NAME: C_0805-10UF,X6S,10%,25V,032-0728-000-032-0728-000,10UF; CDS_SEC: 1; CHIPS_PART_NAME: C; DEVICE_TYPENAME: C_0805-10UFX6S1025V032-0728-000-032-0728-00010UF; DRAWING: @P3768_A04_LIB.P3768_A04(SCH_1):PAGE9; MAT: X6S; MAX_VOLTAGE: 25V; NV_PN: 032-0728-000; PACK_TYPE: 0805; PATH: I143; PHYS_PAGE: 9; PSPICETEMPLATE: X^@REFDES  %1    %2   @NV_PN; ROT: 0; SEC: 1; SIGNAL_MODEL: nv_cap; TOL: 10%; VER: 1; XY: (-4400,5600)
C316 = C#1: ASSEMBLY: PS_5V; CDS_LIB: discrete; CDS_PART_NAME: C_0603-1UF,X7R,10%,25V,032-0253-000; CDS_PHYS_PART_NAME: C_0603-1UF,X7R,10%,25V,032-0253-000-032-0253-000,1UF; CDS_SEC: 1; CHIPS_PART_NAME: C; DEVICE_TYPENAME: C_0603-1UFX7R1025V032-0253-000-032-0253-0001UF; DRAWING: @P3768_A04_LIB.P3768_A04(SCH_1):PAGE9; MAT: X7R; MAX_VOLTAGE: 25V; NV_PN: 032-0253-000; PATH: I190; PHYS_PAGE: 9; PSPICETEMPLATE: X^@REFDES  %1    %2   @NV_PN; ROT: 0; SEC: 1; SIGNAL_MODEL: nv_cap; TOL: 10%; VER: 1; XY: (-4750,5600)
C317 = C#1: ASSEMBLY: PS_5V; CDS_LIB: discrete; CDS_PART_NAME: C_0805-10UF,X6S,10%,25V,032-0728-000; CDS_PHYS_PART_NAME: C_0805-10UF,X6S,10%,25V,032-0728-000-032-0728-000,10UF; CDS_SEC: 1; CHIPS_PART_NAME: C; DEVICE_TYPENAME: C_0805-10UFX6S1025V032-0728-000-032-0728-00010UF; DRAWING: @P3768_A04_LIB.P3768_A04(SCH_1):PAGE9; MAT: X6S; MAX_VOLTAGE: 25V; NV_PN: 032-0728-000; PACK_TYPE: 0805; PATH: I142; PHYS_PAGE: 9; PSPICETEMPLATE: X^@REFDES  %1    %2   @NV_PN; ROT: 0; SEC: 1; SIGNAL_MODEL: nv_cap; TOL: 10%; VER: 1; XY: (-4050,5600)
C318 = C: ASSEMBLY: PS_5V; CDS_LIB: discrete; CDS_PART_NAME: C_0402-1NF,X7R,10%,16V,036-0012-000; CDS_PHYS_PART_NAME: C_0402-1NF,X7R,10%,16V,036-0012-000-036-0012-000,1NF; CDS_SEC: 1; DEVICE_TYPENAME: C_0402-1NFX7R1016V036-0012-000-036-0012-0001NF; DRAWING: @P3768_A04_LIB.P3768_A04(SCH_1):PAGE9; MAT: X7R; MAX_VOLTAGE: 16V; NV_PN: 036-0012-000; PATH: I158; PHYS_PAGE: 9; PSPICETEMPLATE: X^@REFDES  %1    %2   @NV_PN; ROT: 0; SEC: 1; SIGNAL_MODEL: nv_cap; SKU: DNI; TOL: 10%; VER: 2; XY: (-4250,3350)
C319 = C#1: ASSEMBLY: PS_5V; CDS_LIB: discrete; CDS_PART_NAME: C_0402-0.1UF,X5R,20%,25V,039-0208-000; CDS_PHYS_PART_NAME: C_0402-0.1UF,X5R,20%,25V,039-0208-000-0.1UF,039-0208-000; CDS_SEC: 1; CHIPS_PART_NAME: C; DEVICE_TYPENAME: C_0402-01UFX5R2025V039-0208-000-01UF039-0208-000; DRAWING: @P3768_A04_LIB.P3768_A04(SCH_1):PAGE9; MAT: X5R; MAX_VOLTAGE: 25V; NV_PN: 039-0208-000; PATH: I193; PHYS_PAGE: 9; ROT: 0; SEC: 1; SIGNAL_MODEL: nv_cap; TOL: 20%; VER: 1; XY: (-5100,5600)
C320 = C#1: ASSEMBLY: PS_5V; CDS_LIB: discrete; CDS_PART_NAME: C_0805-10UF,X6S,10%,25V,032-0728-000; CDS_PHYS_PART_NAME: C_0805-10UF,X6S,10%,25V,032-0728-000-032-0728-000,10UF; CDS_SEC: 1; CHIPS_PART_NAME: C; DEVICE_TYPENAME: C_0805-10UFX6S1025V032-0728-000-032-0728-00010UF; DRAWING: @P3768_A04_LIB.P3768_A04(SCH_1):PAGE9; MAT: X6S; MAX_VOLTAGE: 25V; NV_PN: 032-0728-000; PACK_TYPE: 0805; PATH: I141; PHYS_PAGE: 9; PSPICETEMPLATE: X^@REFDES  %1    %2   @NV_PN; ROT: 0; SEC: 1; SIGNAL_MODEL: nv_cap; TOL: 10%; VER: 1; XY: (-3700,5600)
C321 = C#1: ASSEMBLY: PS_5V; CDS_LIB: discrete; CDS_PART_NAME: C_1206-22UF,X6S,10%,25V,032-1215-000; CDS_PHYS_PART_NAME: C_1206-22UF,X6S,10%,25V,032-1215-000-032-1215-000,22UF; CDS_SEC: 1; CHIPS_PART_NAME: C; DEVICE_TYPENAME: C_1206-22UFX6S1025V032-1215-000-032-1215-00022UF; DRAWING: @P3768_A04_LIB.P3768_A04(SCH_1):PAGE9; MAT: X6S; MAX_VOLTAGE: 25V; NV_PN: 032-1215-000; PACK_TYPE: 1206; PATH: I192; PHYS_PAGE: 9; ROT: 0; SEC: 1; SIGNAL_MODEL: nv_cap; TOL: 10%; VER: 1; XY: (-3300,5600)
C322 = C#1: ASSEMBLY: PS_5V; CDS_LIB: discrete; CDS_PART_NAME: C_0402-330PF,C0G,5%,50V,035-0066-000; CDS_PHYS_PART_NAME: C_0402-330PF,C0G,5%,50V,035-0066-000-035-0066-000,330PF; CDS_SEC: 1; CHIPS_PART_NAME: C; DEVICE_TYPENAME: C_0402-330PFC0G550V035-0066-000-035-0066-000330PF; DRAWING: @P3768_A04_LIB.P3768_A04(SCH_1):PAGE9; MAT: C0G; MAX_VOLTAGE: 50V; NV_PN: 035-0066-000; PATH: I156; PHYS_PAGE: 9; PSPICETEMPLATE: X^@REFDES  %1    %2   @NV_PN; ROT: 0; SEC: 1; SIGNAL_MODEL: nv_cap; TOL: 5%; VER: 1; XY: (-3500,3100)
C323 = C#1: ASSEMBLY: PS_5V; CDS_LIB: discrete; CDS_PART_NAME: C_0805-22UF,X6S,20%,16V,032-0559-000; CDS_PHYS_PART_NAME: C_0805-22UF,X6S,20%,16V,032-0559-000-032-0559-000,22UF; CDS_SEC: 1; CHIPS_PART_NAME: C; DEVICE_TYPENAME: C_0805-22UFX6S2016V032-0559-000-032-0559-00022UF; DRAWING: @P3768_A04_LIB.P3768_A04(SCH_1):PAGE9; MAT: X6S; MAX_VOLTAGE: 16V; NV_PN: 032-0559-000; PACK_TYPE: 0805; PATH: I149; PHYS_PAGE: 9; PSPICETEMPLATE: X^@REFDES  %1    %2   @NV_PN; ROT: 0; SEC: 1; SIGNAL_MODEL: nv_cap; TOL: 20%; VER: 1; XY: (-2700,3850)
C324 = C#1: ASSEMBLY: PS_5V; CDS_LIB: discrete; CDS_PART_NAME: C_0805-22UF,X6S,20%,16V,032-0559-000; CDS_PHYS_PART_NAME: C_0805-22UF,X6S,20%,16V,032-0559-000-032-0559-000,22UF; CDS_SEC: 1; CHIPS_PART_NAME: C; DEVICE_TYPENAME: C_0805-22UFX6S2016V032-0559-000-032-0559-00022UF; DRAWING: @P3768_A04_LIB.P3768_A04(SCH_1):PAGE9; MAT: X6S; MAX_VOLTAGE: 16V; NV_PN: 032-0559-000; PACK_TYPE: 0805; PATH: I150; PHYS_PAGE: 9; PSPICETEMPLATE: X^@REFDES  %1    %2   @NV_PN; ROT: 0; SEC: 1; SIGNAL_MODEL: nv_cap; TOL: 20%; VER: 1; XY: (-2350,3850)
C325 = C#1: ASSEMBLY: PS_5V; CDS_LIB: discrete; CDS_PART_NAME: C_0402-0.1UF,X7R,10%,16V,032-0793-000; CDS_PHYS_PART_NAME: C_0402-0.1UF,X7R,10%,16V,032-0793-000-0.1UF,032-0793-000; CDS_SEC: 1; CHIPS_PART_NAME: C; DEVICE_TYPENAME: C_0402-01UFX7R1016V032-0793-000-01UF032-0793-000; DRAWING: @P3768_A04_LIB.P3768_A04(SCH_1):PAGE9; MAT: X7R; MAX_VOLTAGE: 16V; NV_PN: 032-0793-000; PATH: I151; PHYS_PAGE: 9; PSPICETEMPLATE: X^@REFDES  %1    %2   @NV_PN; ROT: 0; SEC: 1; SIGNAL_MODEL: nv_cap; TOL: 10%; VER: 1; XY: (-3400,3850)
C326 = C_POL: ASSEMBLY: PS_5V; CDS_LIB: discrete; CDS_PART_NAME: C_POL_SMD_3528-150UF,TA-POLYMER,20%,6.3V@105DEGC,0.025OHM,9.999UH,2.3A@45DEGC,100KHZ,032-0681-000; CDS_PHYS_PART_NAME: C_POL_SMD_3528-150UF,TA-POLYMER,20%,6.3V@105DEGC,0.025OHM,9.999UH,2.3A@45DEGC,100KHZ,032-0681-000-032-0681-000,150UF; CDS_SEC: 1; DEVICE_TYPENAME: C_POL_SMD_3528-150UFTA-POLYMER2063V105DEGC0025OHM9999UH23A45DEGC100KHZ032-0681-000-032-0681-000150UF; DRAWING: @P3768_A04_LIB.P3768_A04(SCH_1):PAGE9; ESL: 9.999uH; ESR: 0.025ohm; MAT: TA-Polymer; MAX_VOLTAGE: 6.3V@105degC; NV_PN: 032-0681-000; PACK_TYPE: SMD_3528; PATH: I184; PHYS_PAGE: 9; RIPPLE_CURRENT: 2.3A@45degC,100KHz; ROT: 0; SEC: 1; SIGNAL_MODEL: nv_capp; TOL: 20%; VER: 1; XY: (-900,3850)
C401 = C#1: ASSEMBLY: PS_3V3; CDS_LIB: discrete; CDS_PART_NAME: C_0805-22UF,X6S,20%,16V,032-0559-000; CDS_PHYS_PART_NAME: C_0805-22UF,X6S,20%,16V,032-0559-000-032-0559-000,22UF; CDS_SEC: 1; CHIPS_PART_NAME: C; DEVICE_TYPENAME: C_0805-22UFX6S2016V032-0559-000-032-0559-00022UF; DRAWING: @P3768_A04_LIB.P3768_A04(SCH_1):PAGE9; MAT: X6S; MAX_VOLTAGE: 16V; NV_PN: 032-0559-000; PACK_TYPE: 0805; PATH: I185; PHYS_PAGE: 9; PSPICETEMPLATE: X^@REFDES  %1    %2   @NV_PN; ROT: 0; SEC: 1; SIGNAL_MODEL: nv_cap; TOL: 20%; VER: 1; XY: (-3050,3850)
C405 = C#1: ASSEMBLY: PS_5V; CDS_LIB: discrete; CDS_PART_NAME: C_0805-22UF,X6S,20%,16V,032-0559-000; CDS_PHYS_PART_NAME: C_0805-22UF,X6S,20%,16V,032-0559-000-032-0559-000,22UF; CDS_SEC: 1; CHIPS_PART_NAME: C; DEVICE_TYPENAME: C_0805-22UFX6S2016V032-0559-000-032-0559-00022UF; DRAWING: @P3768_A04_LIB.P3768_A04(SCH_1):PAGE9; MAT: X6S; MAX_VOLTAGE: 16V; NV_PN: 032-0559-000; PACK_TYPE: 0805; PATH: I200; PHYS_PAGE: 9; PSPICETEMPLATE: X^@REFDES  %1    %2   @NV_PN; ROT: 0; SEC: 1; SIGNAL_MODEL: nv_cap; SKU: DNI; TOL: 20%; VER: 1; XY: (-2000,3850)
C406 = C#1: ASSEMBLY: PS_5V; CDS_LIB: discrete; CDS_PART_NAME: C_0805-22UF,X6S,20%,16V,032-0559-000; CDS_PHYS_PART_NAME: C_0805-22UF,X6S,20%,16V,032-0559-000-032-0559-000,22UF; CDS_SEC: 1; CHIPS_PART_NAME: C; DEVICE_TYPENAME: C_0805-22UFX6S2016V032-0559-000-032-0559-00022UF; DRAWING: @P3768_A04_LIB.P3768_A04(SCH_1):PAGE9; MAT: X6S; MAX_VOLTAGE: 16V; NV_PN: 032-0559-000; PACK_TYPE: 0805; PATH: I201; PHYS_PAGE: 9; PSPICETEMPLATE: X^@REFDES  %1    %2   @NV_PN; ROT: 0; SEC: 1; SIGNAL_MODEL: nv_cap; SKU: DNI; TOL: 20%; VER: 1; XY: (-1650,3850)
C407 = C#1: ASSEMBLY: PS_5V; CDS_LIB: discrete; CDS_PART_NAME: C_0805-22UF,X6S,20%,16V,032-0559-000; CDS_PHYS_PART_NAME: C_0805-22UF,X6S,20%,16V,032-0559-000-032-0559-000,22UF; CDS_SEC: 1; CHIPS_PART_NAME: C; DEVICE_TYPENAME: C_0805-22UFX6S2016V032-0559-000-032-0559-00022UF; DRAWING: @P3768_A04_LIB.P3768_A04(SCH_1):PAGE9; MAT: X6S; MAX_VOLTAGE: 16V; NV_PN: 032-0559-000; PACK_TYPE: 0805; PATH: I202; PHYS_PAGE: 9; PSPICETEMPLATE: X^@REFDES  %1    %2   @NV_PN; ROT: 0; SEC: 1; SIGNAL_MODEL: nv_cap; SKU: DNI; TOL: 20%; VER: 1; XY: (-1300,3850)
L42 = L: ASSEMBLY: PS_5V; CDS_LIB: discrete; CDS_PART_NAME: L_7_6X7_6-2.2UH,ALLOY POWDER,20%,10A,12A,0.0125OHM,50@300KHZ,0HZ,130-1236-000; CDS_PHYS_PART_NAME: L_7_6X7_6-2.2UH,ALLOY POWDER,20%,10A,12A,0.0125OHM,50@300KHZ,0HZ,130-1236-000-130-1236-000,2.2UH; CDS_SEC: 1; CONTINUOUS_CURRENT: 10A; DC_RESISTANCE: 0.0125ohm; DEVICE_TYPENAME: L_7_6X7_6-22UHALLOYPOWDER2010A12A00125OHM50300KHZ0HZ130-1236-000-130-1236-00022UH; DRAWING: @P3768_A04_LIB.P3768_A04(SCH_1):PAGE9; MAT: Alloy Powder; MAX_CURRENT: 12A; NV_PN: 130-1236-000; PACK_TYPE: 7_6X7_6; PATH: I199; PHYS_PAGE: 9; Q: 50@300KHz; ROT: 0; SEC: 1; SELF_RESONANCE_FREQ: 0Hz; SIGNAL_MODEL: nv_ind; SKU: DNI; TOL: 20%; VER: 1; XY: (-4550,4400)
L43 = L: ASSEMBLY: PS_5V; CDS_LIB: discrete; CDS_PART_NAME: L_7_6X7_6-2.7UH,COMPOSITE,20%,9.2A,12.8A,0.0173OHM,[ ]@[ ],32MHZ,130-1439-000; CDS_PHYS_PART_NAME: L_7_6X7_6-2.7UH,COMPOSITE,20%,9.2A,12.8A,0.0173OHM,[ ]@[ ],32MHZ,130-1439-000-130-1439-000,2.7UH; CDS_SEC: 1; CONTINUOUS_CURRENT: 9.2A; DC_RESISTANCE: 0.0173ohm; DEVICE_TYPENAME: L_7_6X7_6-27UHCOMPOSITE2092A128A00173OHM32MHZ130-1439-000-130-1439-00027UH; DRAWING: @P3768_A04_LIB.P3768_A04(SCH_1):PAGE9; MAT: Composite; MAX_CURRENT: 12.8A; NV_PN: 130-1439-000; PACK_TYPE: 7_6X7_6; PATH: I198; PHYS_PAGE: 9; Q: [ ]@[ ]; ROT: 0; SEC: 1; SELF_RESONANCE_FREQ: 32MHz; SIGNAL_MODEL: nv_ind; SKU: DNI; TOL: 20%; VER: 1; XY: (-4550,4200)
L44 = L: ASSEMBLY: PS_5V; CDS_LIB: discrete; CDS_PART_NAME: L_7_6X7_6-3.3UH,COMPOSITE,20%,10A,12.3A,0.02145OHM,[ ]@[ ],29MHZ,130-1404-000; CDS_PHYS_PART_NAME: L_7_6X7_6-3.3UH,COMPOSITE,20%,10A,12.3A,0.02145OHM,[ ]@[ ],29MHZ,130-1404-000-130-1404-000,3.3UH; CDS_SEC: 1; CONTINUOUS_CURRENT: 10A; DC_RESISTANCE: 0.02145ohm; DEVICE_TYPENAME: L_7_6X7_6-33UHCOMPOSITE2010A123A002145OHM29MHZ130-1404-000-130-1404-00033UH; DRAWING: @P3768_A04_LIB.P3768_A04(SCH_1):PAGE9; MAT: Composite; MAX_CURRENT: 12.3A; NV_PN: 130-1404-000; PACK_TYPE: 7_6X7_6; PATH: I197; PHYS_PAGE: 9; Q: [ ]@[ ]; ROT: 0; SEC: 1; SELF_RESONANCE_FREQ: 29MHz; SIGNAL_MODEL: nv_ind; TOL: 20%; VER: 1; XY: (-4550,4000)
R387 = R: ASSEMBLY: PS_5V; CDS_LIB: discrete; CDS_PART_NAME: R_0402-56K,5 %,62.5MW,195-0613-000; CDS_PHYS_PART_NAME: R_0402-56K,5 %,62.5MW,195-0613-000-195-0613-000,56K; CDS_SEC: 1; DEVICE_TYPENAME: R_0402-56K5625MW195-0613-000-195-0613-00056K; DRAWING: @P3768_A04_LIB.P3768_A04(SCH_1):PAGE9; MAX_WATTAGE: 62.5mW; NV_PN: 195-0613-000; PATH: I169; PHYS_PAGE: 9; ROT: 0; SEC: 1; SIGNAL_MODEL: nv_res; TOL: 5 %; VER: 2; XY: (-10200,4100)
R388 = R: ASSEMBLY: PS_5V; CDS_LIB: discrete; CDS_PART_NAME: R_0402-10K,5 %,62.5MW,195-0486-000; CDS_PHYS_PART_NAME: R_0402-10K,5 %,62.5MW,195-0486-000-10K,195-0486-000; CDS_SEC: 1; DEVICE_TYPENAME: R_0402-10K5625MW195-0486-000-10K195-0486-000; DRAWING: @P3768_A04_LIB.P3768_A04(SCH_1):PAGE9; MAX_WATTAGE: 62.5mW; NV_PN: 195-0486-000; PATH: I170; PHYS_PAGE: 9; PSPICETEMPLATE: X^@REFDES  %1    %2   @NV_PN; ROT: 0; SEC: 1; SIGNAL_MODEL: nv_res; SKU: DNI; TOL: 5 %; VER: 2; XY: (-10200,3700)
R389 = R#1: ASSEMBLY: PS_5V; CDS_LIB: discrete; CDS_PART_NAME: R_0402-10K,1 %,62.5MW,195-0004-000; CDS_PHYS_PART_NAME: R_0402-10K,1 %,62.5MW,195-0004-000-10K,195-0004-000; CDS_SEC: 1; CHIPS_PART_NAME: R; DEVICE_TYPENAME: R_0402-10K1625MW195-0004-000-10K195-0004-000; DRAWING: @P3768_A04_LIB.P3768_A04(SCH_1):PAGE9; MAX_WATTAGE: 62.5mW; NV_PN: 195-0004-000; PATH: I168; PHYS_PAGE: 9; PSPICETEMPLATE: X^@REFDES  %1    %2   @NV_PN; ROT: 0; SEC: 1; SIGNAL_MODEL: nv_res; TOL: 1 %; VER: 1; XY: (-9250,4200)
R391 = R: ASSEMBLY: PS_5V; CDS_LIB: discrete; CDS_PART_NAME: R_0402-10K,1 %,62.5MW,195-0004-000; CDS_PHYS_PART_NAME: R_0402-10K,1 %,62.5MW,195-0004-000-10K,195-0004-000; CDS_SEC: 1; DEVICE_TYPENAME: R_0402-10K1625MW195-0004-000-10K195-0004-000; DRAWING: @P3768_A04_LIB.P3768_A04(SCH_1):PAGE9; MAX_WATTAGE: 62.5mW; NV_PN: 195-0004-000; PATH: I171; PHYS_PAGE: 9; PSPICETEMPLATE: X^@REFDES  %1    %2   @NV_PN; ROT: 0; SEC: 1; SIGNAL_MODEL: nv_res; SKU: DNI; TOL: 1 %; VER: 2; XY: (-8900,4600)
R392 = R#1: ASSEMBLY: PS_5V; CDS_LIB: discrete; CDS_PART_NAME: R_0402-0OHM,0.05 OHM,62.5MW,195-2655-000; CDS_PHYS_PART_NAME: R_0402-0OHM,0.05 OHM,62.5MW,195-2655-000-0OHM,195-2655-000; CDS_SEC: 1; CHIPS_PART_NAME: R; DEVICE_TYPENAME: R_0402-0OHM005OHM625MW195-2655-000-0OHM195-2655-000; DRAWING: @P3768_A04_LIB.P3768_A04(SCH_1):PAGE9; MAX_WATTAGE: 62.5mW; NV_PN: 195-2655-000; PATH: I167; PHYS_PAGE: 9; PSPICETEMPLATE: X^@REFDES  %1    %2   @NV_PN; ROT: 0; SEC: 1; SIGNAL_MODEL: nv_res; TOL: 0.05 ohm; VER: 1; XY: (-8800,3900)
R393 = R: ASSEMBLY: PS_5V; CDS_LIB: discrete; CDS_PART_NAME: R_0402-0OHM,0.05 OHM,62.5MW,195-2655-000; CDS_PHYS_PART_NAME: R_0402-0OHM,0.05 OHM,62.5MW,195-2655-000-0OHM,195-2655-000; CDS_SEC: 1; DEVICE_TYPENAME: R_0402-0OHM005OHM625MW195-2655-000-0OHM195-2655-000; DRAWING: @P3768_A04_LIB.P3768_A04(SCH_1):PAGE9; MAX_WATTAGE: 62.5mW; NV_PN: 195-2655-000; PATH: I133; PHYS_PAGE: 9; PSPICETEMPLATE: X^@REFDES  %1    %2   @NV_PN; ROT: 2; SEC: 1; SIGNAL_MODEL: nv_res; SKU: DNI; TOL: 0.05 ohm; VER: 2; XY: (-8400,5100)
R394 = R: ASSEMBLY: PS_5V; CDS_LIB: discrete; CDS_PART_NAME: R_0402-100K,1 %,62.5MW,195-0005-000; CDS_PHYS_PART_NAME: R_0402-100K,1 %,62.5MW,195-0005-000-100K,195-0005-000; CDS_SEC: 1; DEVICE_TYPENAME: R_0402-100K1625MW195-0005-000-100K195-0005-000; DRAWING: @P3768_A04_LIB.P3768_A04(SCH_1):PAGE9; MAX_WATTAGE: 62.5mW; NV_PN: 195-0005-000; PATH: I164; PHYS_PAGE: 9; PSPICETEMPLATE: X^@REFDES  %1    %2   @NV_PN; ROT: 0; SEC: 1; SIGNAL_MODEL: nv_res; SKU: DNI; TOL: 1 %; VER: 2; XY: (-8400,3500)
R395 = R#1: ASSEMBLY: PS_5V; CDS_LIB: discrete; CDS_PART_NAME: R_0402-0OHM,0.05 OHM,62.5MW,195-2655-000; CDS_PHYS_PART_NAME: R_0402-0OHM,0.05 OHM,62.5MW,195-2655-000-0OHM,195-2655-000; CDS_SEC: 1; CHIPS_PART_NAME: R; DEVICE_TYPENAME: R_0402-0OHM005OHM625MW195-2655-000-0OHM195-2655-000; DRAWING: @P3768_A04_LIB.P3768_A04(SCH_1):PAGE9; MAX_WATTAGE: 62.5mW; NV_PN: 195-2655-000; PATH: I194; PHYS_PAGE: 9; ROT: 0; SEC: 1; SIGNAL_MODEL: nv_res; SKU: DNI; TOL: 0.05 ohm; VER: 1; XY: (-8300,4650)
R396 = R#1: ASSEMBLY: PS_5V; CDS_LIB: discrete; CDS_PART_NAME: R_0402-0OHM,0.05 OHM,62.5MW,195-2655-000; CDS_PHYS_PART_NAME: R_0402-0OHM,0.05 OHM,62.5MW,195-2655-000-0OHM,195-2655-000; CDS_SEC: 1; CHIPS_PART_NAME: R; DEVICE_TYPENAME: R_0402-0OHM005OHM625MW195-2655-000-0OHM195-2655-000; DRAWING: @P3768_A04_LIB.P3768_A04(SCH_1):PAGE9; MAX_WATTAGE: 62.5mW; NV_PN: 195-2655-000; PATH: I132; PHYS_PAGE: 9; PSPICETEMPLATE: X^@REFDES  %1    %2   @NV_PN; ROT: 0; SEC: 1; SIGNAL_MODEL: nv_res; SKU: DNI; TOL: 0.05 ohm; VER: 1; XY: (-8100,5400)
R397 = R#1: ASSEMBLY: PS_5V; CDS_LIB: discrete; CDS_PART_NAME: R_0402-10K,1 %,62.5MW,195-0004-000; CDS_PHYS_PART_NAME: R_0402-10K,1 %,62.5MW,195-0004-000-10K,195-0004-000; CDS_SEC: 1; CHIPS_PART_NAME: R; DEVICE_TYPENAME: R_0402-10K1625MW195-0004-000-10K195-0004-000; DRAWING: @P3768_A04_LIB.P3768_A04(SCH_1):PAGE9; MAX_WATTAGE: 62.5mW; NV_PN: 195-0004-000; PATH: I195; PHYS_PAGE: 9; ROT: 0; SEC: 1; SIGNAL_MODEL: nv_res; TOL: 1 %; VER: 1; XY: (-7750,4650)
R398 = R#1: ASSEMBLY: PS_5V; CDS_LIB: discrete; CDS_PART_NAME: R_0402-10K,1 %,62.5MW,195-0004-000; CDS_PHYS_PART_NAME: R_0402-10K,1 %,62.5MW,195-0004-000-10K,195-0004-000; CDS_SEC: 1; CHIPS_PART_NAME: R; DEVICE_TYPENAME: R_0402-10K1625MW195-0004-000-10K195-0004-000; DRAWING: @P3768_A04_LIB.P3768_A04(SCH_1):PAGE9; MAX_WATTAGE: 62.5mW; NV_PN: 195-0004-000; PATH: I166; PHYS_PAGE: 9; PSPICETEMPLATE: X^@REFDES  %1    %2   @NV_PN; ROT: 0; SEC: 1; SIGNAL_MODEL: nv_res; SKU: DNI; TOL: 1 %; VER: 1; XY: (-7700,4050)
R399 = R#1: ASSEMBLY: PS_5V; CDS_LIB: discrete; CDS_PART_NAME: R_0402-0OHM,0.05 OHM,62.5MW,195-2655-000; CDS_PHYS_PART_NAME: R_0402-0OHM,0.05 OHM,62.5MW,195-2655-000-0OHM,195-2655-000; CDS_SEC: 1; CHIPS_PART_NAME: R; DEVICE_TYPENAME: R_0402-0OHM005OHM625MW195-2655-000-0OHM195-2655-000; DRAWING: @P3768_A04_LIB.P3768_A04(SCH_1):PAGE9; MAX_WATTAGE: 62.5mW; NV_PN: 195-2655-000; PATH: I136; PHYS_PAGE: 9; ROT: 0; SEC: 1; SIGNAL_MODEL: nv_res; TOL: 0.05 ohm; VER: 1; XY: (-6500,5750)
R400 = R: ASSEMBLY: PS_5V; CDS_LIB: discrete; CDS_PART_NAME: R_0402-30.1K,1 %,62.5MW,195-0235-000; CDS_PHYS_PART_NAME: R_0402-30.1K,1 %,62.5MW,195-0235-000-195-0235-000,30.1K; CDS_SEC: 1; DEVICE_TYPENAME: R_0402-301K1625MW195-0235-000-195-0235-000301K; DRAWING: @P3768_A04_LIB.P3768_A04(SCH_1):PAGE9; MAX_WATTAGE: 62.5mW; NV_PN: 195-0235-000; PATH: I162; PHYS_PAGE: 9; ROT: 0; SEC: 1; SIGNAL_MODEL: nv_res; SKU: DNI; TOL: 1 %; VER: 2; XY: (-6150,3550)
R401 = R: ASSEMBLY: PS_5V; CDS_LIB: discrete; CDS_PART_NAME: R_0402-0OHM,0.01 OHM,0.125W,195-1691-000; CDS_PHYS_PART_NAME: R_0402-0OHM,0.01 OHM,0.125W,195-1691-000-0OHM,195-1691-000; CDS_SEC: 1; DEVICE_TYPENAME: R_0402-0OHM001OHM0125W195-1691-000-0OHM195-1691-000; DRAWING: @P3768_A04_LIB.P3768_A04(SCH_1):PAGE9; MAX_WATTAGE: 0.125W; NV_PN: 195-1691-000; PATH: I163; PHYS_PAGE: 9; ROT: 0; SEC: 1; SIGNAL_MODEL: nv_res; TOL: 0.01 ohm; VER: 2; XY: (-6150,3150)
R402 = R#1: ASSEMBLY: PS_5V; CDS_LIB: discrete; CDS_PART_NAME: R_0402-715K,1 %,62.5MW,195-0416-000; CDS_PHYS_PART_NAME: R_0402-715K,1 %,62.5MW,195-0416-000-195-0416-000,715K; CDS_SEC: 1; CHIPS_PART_NAME: R; DEVICE_TYPENAME: R_0402-715K1625MW195-0416-000-195-0416-000715K; DRAWING: @P3768_A04_LIB.P3768_A04(SCH_1):PAGE9; MAX_WATTAGE: 62.5mW; NV_PN: 195-0416-000; PATH: I204; PHYS_PAGE: 9; ROT: 0; SEC: 1; TOL: 1 %; VER: 1; XY: (-5600,4700)
R403 = R#1: ASSEMBLY: PS_5V; CDS_LIB: discrete; CDS_PART_NAME: R_0402-200K,1 %,62.5MW,195-0151-000; CDS_PHYS_PART_NAME: R_0402-200K,1 %,62.5MW,195-0151-000-195-0151-000,200K; CDS_SEC: 1; CHIPS_PART_NAME: R; DEVICE_TYPENAME: R_0402-200K1625MW195-0151-000-195-0151-000200K; DRAWING: @P3768_A04_LIB.P3768_A04(SCH_1):PAGE9; MAX_WATTAGE: 62.5mW; NV_PN: 195-0151-000; PATH: I161; PHYS_PAGE: 9; PSPICETEMPLATE: X^@REFDES  %1    %2   @NV_PN; ROT: 0; SEC: 1; SIGNAL_MODEL: nv_res; TOL: 1 %; VER: 1; XY: (-5400,3750)
R404 = R: ASSEMBLY: PS_5V; CDS_LIB: discrete; CDS_PART_NAME: R_0402-100OHM,1 %,62.5MW,195-0002-000; CDS_PHYS_PART_NAME: R_0402-100OHM,1 %,62.5MW,195-0002-000-100OHM,195-0002-000; CDS_SEC: 1; DEVICE_TYPENAME: R_0402-100OHM1625MW195-0002-000-100OHM195-0002-000; DRAWING: @P3768_A04_LIB.P3768_A04(SCH_1):PAGE9; MAX_WATTAGE: 62.5mW; NV_PN: 195-0002-000; PATH: I154; PHYS_PAGE: 9; PSPICETEMPLATE: X^@REFDES  %1    %2   @NV_PN; ROT: 0; SEC: 1; SIGNAL_MODEL: nv_res; TOL: 1 %; VER: 2; XY: (-3800,3600)
R405 = R: ASSEMBLY: PS_5V; CDS_LIB: discrete; CDS_PART_NAME: R_0402-56.2K,1 %,62.5MW,195-0365-000; CDS_PHYS_PART_NAME: R_0402-56.2K,1 %,62.5MW,195-0365-000-195-0365-000,56.2K; CDS_SEC: 1; DEVICE_TYPENAME: R_0402-562K1625MW195-0365-000-195-0365-000562K; DRAWING: @P3768_A04_LIB.P3768_A04(SCH_1):PAGE9; MAX_WATTAGE: 62.5mW; NV_PN: 195-0365-000; PATH: I205; PHYS_PAGE: 9; ROT: 0; SEC: 1; TOL: 1 %; VER: 2; XY: (-3800,3150)
R406 = R: ASSEMBLY: PS_5V; CDS_LIB: discrete; CDS_PART_NAME: R_0402-10K,1 %,62.5MW,195-0004-000; CDS_PHYS_PART_NAME: R_0402-10K,1 %,62.5MW,195-0004-000-10K,195-0004-000; CDS_SEC: 1; DEVICE_TYPENAME: R_0402-10K1625MW195-0004-000-10K195-0004-000; DRAWING: @P3768_A04_LIB.P3768_A04(SCH_1):PAGE9; MAX_WATTAGE: 62.5mW; NV_PN: 195-0004-000; PATH: I179; PHYS_PAGE: 9; ROT: 0; SEC: 1; SIGNAL_MODEL: nv_res; TOL: 1 %; VER: 2; XY: (-3800,2750)
R407 = R#1: ASSEMBLY: PS_5V; CDS_LIB: discrete; CDS_PART_NAME: R_0402-0OHM,0.05 OHM,62.5MW,195-2655-000; CDS_PHYS_PART_NAME: R_0402-0OHM,0.05 OHM,62.5MW,195-2655-000-0OHM,195-2655-000; CDS_SEC: 1; CHIPS_PART_NAME: R; DEVICE_TYPENAME: R_0402-0OHM005OHM625MW195-2655-000-0OHM195-2655-000; DRAWING: @P3768_A04_LIB.P3768_A04(SCH_1):PAGE9; MAX_WATTAGE: 62.5mW; NV_PN: 195-2655-000; PATH: I153; PHYS_PAGE: 9; PSPICETEMPLATE: X^@REFDES  %1    %2   @NV_PN; ROT: 0; SEC: 1; SIGNAL_MODEL: nv_res; TOL: 0.05 ohm; VER: 1; XY: (-2950,3300)
R510 = R#1: ASSEMBLY: PS_5V; CDS_LIB: discrete; CDS_PART_NAME: R_0402-0OHM,0.05 OHM,62.5MW,195-2655-000; CDS_PHYS_PART_NAME: R_0402-0OHM,0.05 OHM,62.5MW,195-2655-000-0OHM,195-2655-000; CDS_SEC: 1; CHIPS_PART_NAME: R; DEVICE_TYPENAME: R_0402-0OHM005OHM625MW195-2655-000-0OHM195-2655-000; DRAWING: @P3768_A04_LIB.P3768_A04(SCH_1):PAGE9; MAX_WATTAGE: 62.5mW; NV_PN: 195-2655-000; PATH: I203; PHYS_PAGE: 9; PSPICETEMPLATE: X^@REFDES  %1    %2   @NV_PN; ROT: 0; SEC: 1; SIGNAL_MODEL: nv_res; TOL: 0.05 ohm; VER: 1; XY: (-6050,4550)
U3 = U_BUCK_FET_1PH: ASSEMBLY: PS_5V; CDS_LIB: power_supply; CDS_PART_NAME: U_BUCK_FET_1PH_QFN23_NOVR-GS9230NVTQ-R,BUCK,1PH,600KHZ,NONE,0.795V..20V,1%,0.795V,28V,11A,2.5W,316-0538-000; CDS_PHYS_PART_NAME: U_BUCK_FET_1PH_QFN23_NOVR-GS9230NVTQ-R,BUCK,1PH,600KHZ,NONE,0.795V..20V,1%,0.795V,28V,11A,2.5W,316-0538-000-0.795V,316-0538-000; CDS_SEC: 1; DEVICE_TYPENAME: U_BUCK_FET_1PH_QFN23_NOVR-GS9230NVTQ-RBUCK1PH600KHZNONE0795V20V10795V28V11A25W316-0538-000-0795V316-0538-000; DRAWING: @P3768_A04_LIB.P3768_A04(SCH_1):PAGE9; MAX_CURRENT: 11A; MAX_VOLTAGE: 28V; MAX_WATTAGE: 2.5W; MODE: Buck; NV_NAME: GS9230NVTQ-R; NV_PN: 316-0538-000; OUTPUT_VOLTAGE: 0.795V..20V; PACK_TYPE: QFN23_NOVR; PATH: I80; PHASES: 1Ph; PHYS_PAGE: 9; PROGRAMMABLE: None; ROT: 0; SEC: 1; SWITCHING_FREQ: 600KHz; TOL: 1%; VER: 1; XY: (-6900,4150)
U46 = U_VREG_5PIN: ASSEMBLY: PS_5V; CDS_LIB: power_supply; CDS_PART_NAME: U_VREG_5PIN_SOT235-NOEN_B-NCP716BSN500T1G,LOW DROP OUT/FIXED,1.1V@0.15A,4.9V..5.1V,2%,1.2V,24V,0.15A,0.75W,315-1100-000; CDS_PHYS_PART_NAME: U_VREG_5PIN_SOT235-NOEN_B-NCP716BSN500T1G,LOW DROP OUT/FIXED,1.1V@0.15A,4.9V..5.1V,2%,1.2V,24V,0.15A,0.75W,315-1100-000-1.2V,3A; CDS_SEC: 1; DEVICE_TYPENAME: U_VREG_5PIN_SOT235-NOEN_B-NCP716BSN500T1GLOWDROPOUTFIXED11V015A49V51V212V24V015A075W315-1100-000-12V3A; DRAWING: @P3768_A04_LIB.P3768_A04(SCH_1):PAGE9; FORWARD_VOLTAGE: 1.1V@0.15A; MAX_CURRENT: 0.15A; MAX_VOLTAGE: 24V; MAX_WATTAGE: 0.75W; NV_NAME: NCP716BSN500T1G; NV_PN: 315-1100-000; OUTPUT_VOLTAGE: 4.9V..5.1V; PACK_TYPE: SOT235-NOEN_B; PATH: I127; PHYS_PAGE: 9; ROT: 0; SEC: 1; SEC_TYPE: SOT235-NOEN_B; SKU: DNI; TOL: 2%; TYPE: Low Drop Out/Fixed; VER: 18; XY: (-9850,5850)

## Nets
3V3_AO: R523.1 ; also on sheet 13 14 21
5V0_SYS_AIN: C310.1 R396.2 R399.1 U3.7(AIN)
5V0_SYS_BODE: C318.2 C322.1 R404.2 R405.1 R407.1
5V0_SYS_EN: R392.2 R394.1 R398.1 U3.2(EN)
5V0_SYS_EN_R: R387.2 R388.1 R392.1
5V0_SYS_FB: C312.2 C322.2 R405.2 R406.1 U3.5(FB)
5V0_SYS_ISET: R400.2 R401.1 U3.19(PGND5)
5V0_SYS_PFM: R389.2 R391.2 U3.3(PFM*)
5V0_SYS_RJ: C312.1 C314.1 C318.1 R403.2
5V0_SYS_SS: C309.1 U3.23(SS)
5V0_SYS_SW: C311.2 L42.1 L43.1 L44.1 R400.1 R403.1 U3.10(SW1) U3.11(SW2) U3.16(SW3) U3.17(SW4) U3.18(SW5) U3.25(SW6)
5V0_SYS_TON: R402.1 U3.6(TON)
5V0_SYS_VCC: C307.1 R391.1 R393.2 R397.2 R398.2 U3.21(VCC)
5V_BOOT: R510.1 U3.20(BST)
5V_BOOT_R: C311.1 R510.2
5V_LDO_OUT: C300.1 R393.1 R396.1 U46.1(OUT) ; also on sheet 15
GND: C300.2 C305.2 C306.2 C307.2 C309.2 C310.2 C315.2 C316.2 C317.2 C319.2 C320.2 C321.2 C323.2 C324.2 C325.2 C326.2 C401.2 C405.2 C406.2 C407.2 C427.2 Q46.4(S) Q56.2(S) Q57.4(S) R388.2 R389.1 R394.2 R395.1 R401.2 R406.2 R479.2 R524.2 U3.4(AGND) U3.12(PGND1) U3.13(PGND2) U3.14(PGND3) U3.15(PGND4) U46.2(GND) ; also on sheet 1 2 3 4 5 6 7 8 9 10 11 12 13 14 15 18 19 21 25
VDD_5V_SYS: C314.2 C323.1 C324.1 C325.1 C326.1 C401.1 C405.1 C406.1 C407.1 L42.2 L43.2 L44.2 Q48.5(D) R404.1 R407.2 ; also on sheet 1 2 8 9 10 11 12 13 14 15 21
VDD_CVB: C306.1 C315.1 C316.1 C317.1 C319.1 C320.1 C321.1 R387.1 R399.2 R402.2 U3.8(VIN1) U3.9(VIN2) U3.22(VIN3) U3.24(VIN4) U46.3(IN) ; also on sheet 15 18
VDD_CVM: C305.1 Q49.5(D) Q50.5(D) ; also on sheet 13 21
VDD_HV: Q47.5(D) R380.1 R381.1 ; also on sheet 18
VIN_PWR_ON: Q46.5(G) Q57.5(G) ; also on sheet 13
BUCK_5V_PG: R395.2 R397.1 U3.1(PGOOD) ; also on sheet 13 14
CVM_HV_EN: C414.1 C427.1 Q57.2(G) R526.1
CVM_HV_EN*: Q57.6(D) R380.2 R383.1
CVM_MV_EN: C374.1 Q46.2(G) Q56.3(D) R523.2 R524.1
CVM_MV_EN*: Q46.6(D) R381.2 R384.1
HV_AND: C414.2 Q57.1(S) Q57.3(D)
HV_FET_G: C303.2 C403.2 Q47.4(G) Q49.4(G) R383.2 R385.2
HV_FET_S: C303.1 C403.1 Q47.1(S1) Q47.2(S2) Q47.3(S3) Q49.1(S1) Q49.2(S2) Q49.3(S3) R385.1
MODULE_ID: Q56.1(G) R479.1 R526.2 ; also on sheet 21
MV_AND: C374.2 Q46.1(S) Q46.3(D)
MV_FET_G: C304.2 C404.2 Q48.4(G) Q50.4(G) R384.2 R386.2
MV_FET_S: C304.1 C404.1 Q48.1(S1) Q48.2(S2) Q48.3(S3) Q50.1(S1) Q50.2(S2) Q50.3(S3) R386.1
SNN_5V_LDO_NC: U46.4(NC2)
SNN_5V_LDO_NC2: U46.5(NC1)

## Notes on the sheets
sheet 16
- A
- B
- C
- D
- E
- F
- G
- H
- PRE-REG 5V DCDC
- 1
- 1
- 2
- 2
- RTON=715K FSW=408KHz @VIN=19V
- RTON=715K FSW=388KHz @VIN=9V
- PCB CO-LAYOUT
- 3
- 3
- REMOTE SENSE
- 4
- 4
- 5
- 5
- NVIDIA CORPORATION
- 2701 SAN TOMAS EXPRESSWAY
- SANTA CLARA, CA 95050, USA
- ASSEMBLY
- <ASSEMBLY_DESCRIPTION>
- PAGE DETAIL
- PRE-REG 5V
- 600-13768-BASE-400
- NV_PN
- ALL NVIDIA DESIGN SPECIFICATIONS, REFERENCE SPECIFICATIONS, REFERENCE BOARDS, FILES, DRAWINGS, DIAGNOSTICS, LISTS AND OTHER DOCUMENTS OR INFORMATION (TOGETHER AND SEPARATELY, 'MATERIALS') ARE BEING PROVIDED 'AS IS'. THE MATERIALS MAY
- P3768-A04
- 9 OF 25
- CONTAIN KNOWN AND UNKNOWN VIOLATIONS OR DEVIATIONS OF INDUSTRY STANDARDS AND SPECIFICATIONS. NVIDIA MAKES NO WARRANTIES, EXPRESSED, IMPLIED, STATUTORY OR OTHERWISE WITH RESPECT TO THE MATERIALS OR OTHERWISE, AND EXPRESSLY DISCLAIMS ALL
- PCB REV
- PAGE
- IMPLIED WARRANTIES INCLUDING, WITHOUT LIMITATION, THE WARRANTIES OF DESIGN, OF NONINFRINGEMENT, MERCHANTABILITY OR FITNESS FOR A PARTICULAR PURPOSE, OR ARISING FROM A COURSE OF DEALING, TRADE USAGE, TRADE PRACTICE, OR INDUSTRY STANDARDS.
- BOM REV
- A
- DATE
- 27-FEB-2023
- A
- B
- C
- D
- E
- F
- G
- H
sheet 17
- A
- B
- C
- D
- E
- F
- G
- H
- CVM MV/HV POWER MUX
- 1
- 1
- PCB CO-LAYOUT
- 2
- 2
- PCB CO-LAYOUT
- 3
- 3
- 4
- 4
- VIN_PWR_ON
- MODULE_ID
- VDD_CVM
- 0
- 0
- OFF
- 0
- 1
- OFF
- 1
- 0
- 5V
- 1
- 1
- HV
- 5
- 5
- NVIDIA CORPORATION
- 2701 SAN TOMAS EXPRESSWAY
- SANTA CLARA, CA 95050, USA
- ASSEMBLY
- <ASSEMBLY_DESCRIPTION>
- PAGE DETAIL
- CVM POWER MUX
- 600-13768-BASE-400
- NV_PN
- ALL NVIDIA DESIGN SPECIFICATIONS, REFERENCE SPECIFICATIONS, REFERENCE BOARDS, FILES, DRAWINGS, DIAGNOSTICS, LISTS AND OTHER DOCUMENTS OR INFORMATION (TOGETHER AND SEPARATELY, 'MATERIALS') ARE BEING PROVIDED 'AS IS'. THE MATERIALS MAY
- P3768-A04
- 8 OF 25
- CONTAIN KNOWN AND UNKNOWN VIOLATIONS OR DEVIATIONS OF INDUSTRY STANDARDS AND SPECIFICATIONS. NVIDIA MAKES NO WARRANTIES, EXPRESSED, IMPLIED, STATUTORY OR OTHERWISE WITH RESPECT TO THE MATERIALS OR OTHERWISE, AND EXPRESSLY DISCLAIMS ALL
- PCB REV
- PAGE
- IMPLIED WARRANTIES INCLUDING, WITHOUT LIMITATION, THE WARRANTIES OF DESIGN, OF NONINFRINGEMENT, MERCHANTABILITY OR FITNESS FOR A PARTICULAR PURPOSE, OR ARISING FROM A COURSE OF DEALING, TRADE USAGE, TRADE PRACTICE, OR INDUSTRY STANDARDS.
- BOM REV
- A
- DATE
- 27-FEB-2023
- A
- B
- C
- D
- E
- F
- G
- H
